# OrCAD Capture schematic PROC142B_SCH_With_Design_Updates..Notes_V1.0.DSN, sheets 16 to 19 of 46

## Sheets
16 14. CURRENT MEASUREMENT DEVICES: size C; title: SOC SUPPLY RAILS CURRENT MEASUREMENT DEVICES
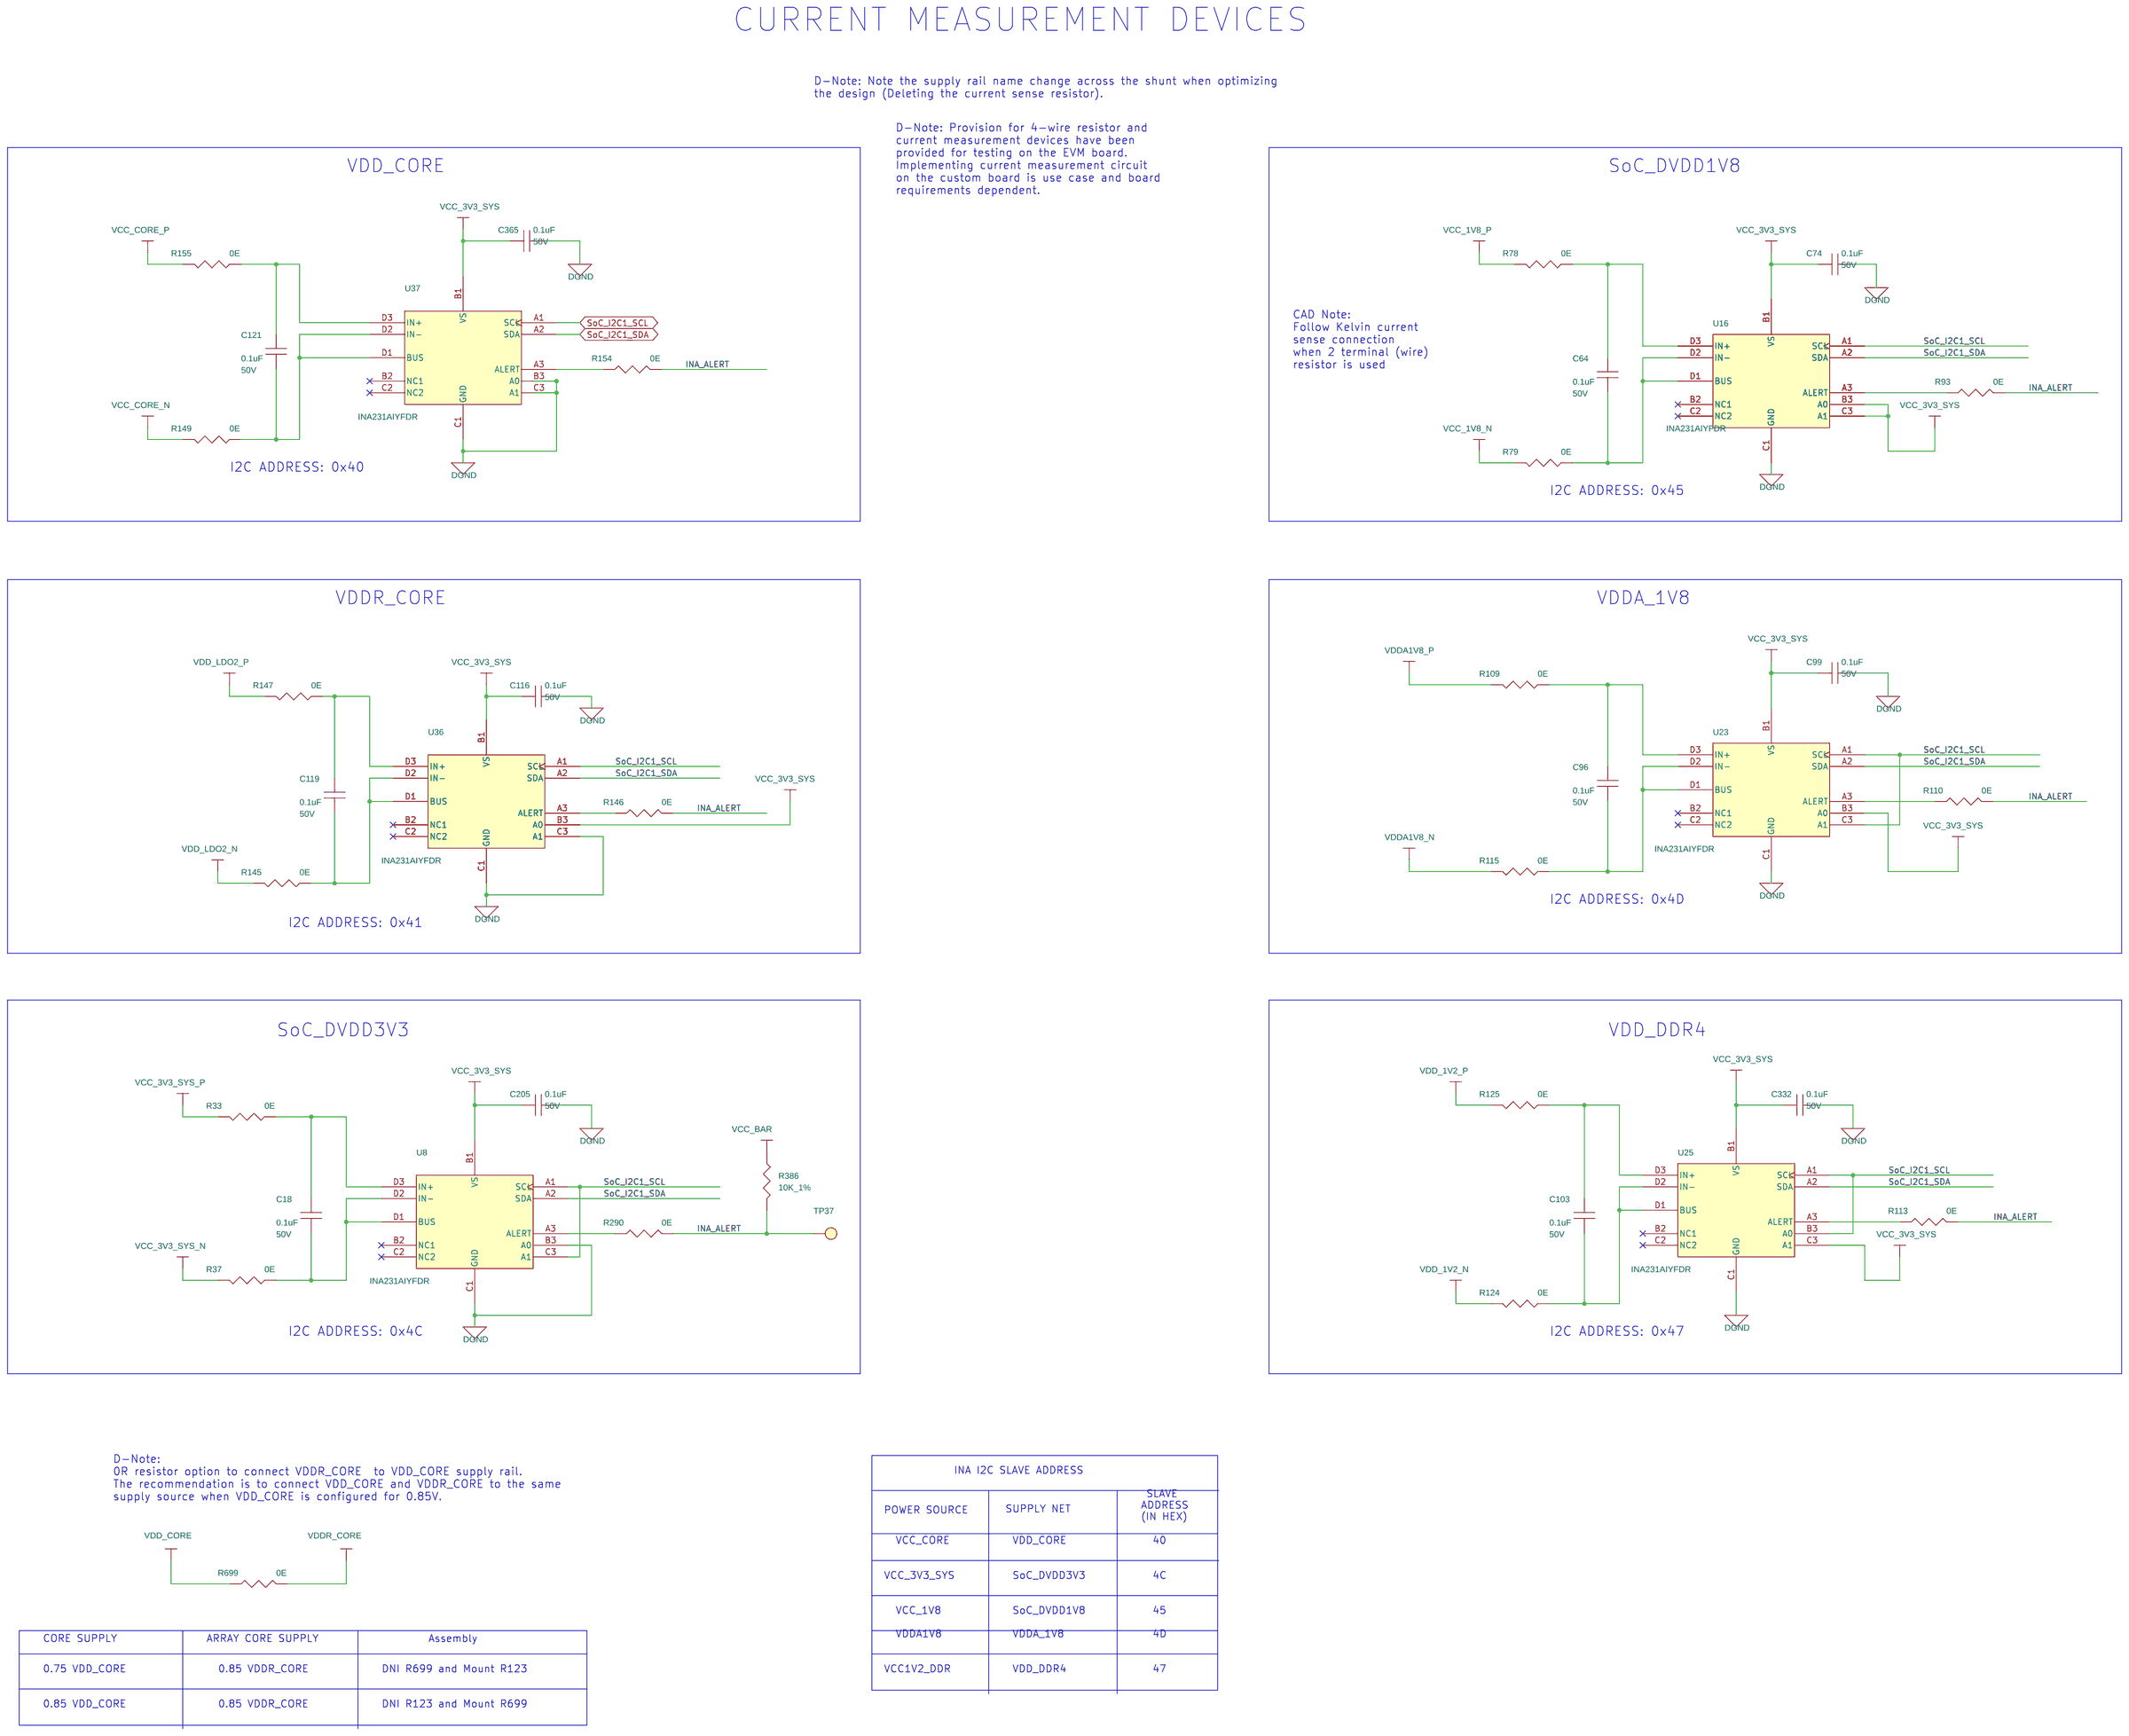
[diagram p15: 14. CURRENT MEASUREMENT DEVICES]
17 15. SOC POWER: size C; title: SOC POWER SUPPLIES, SUPPLY RAILS AND SOC GROUND VSS
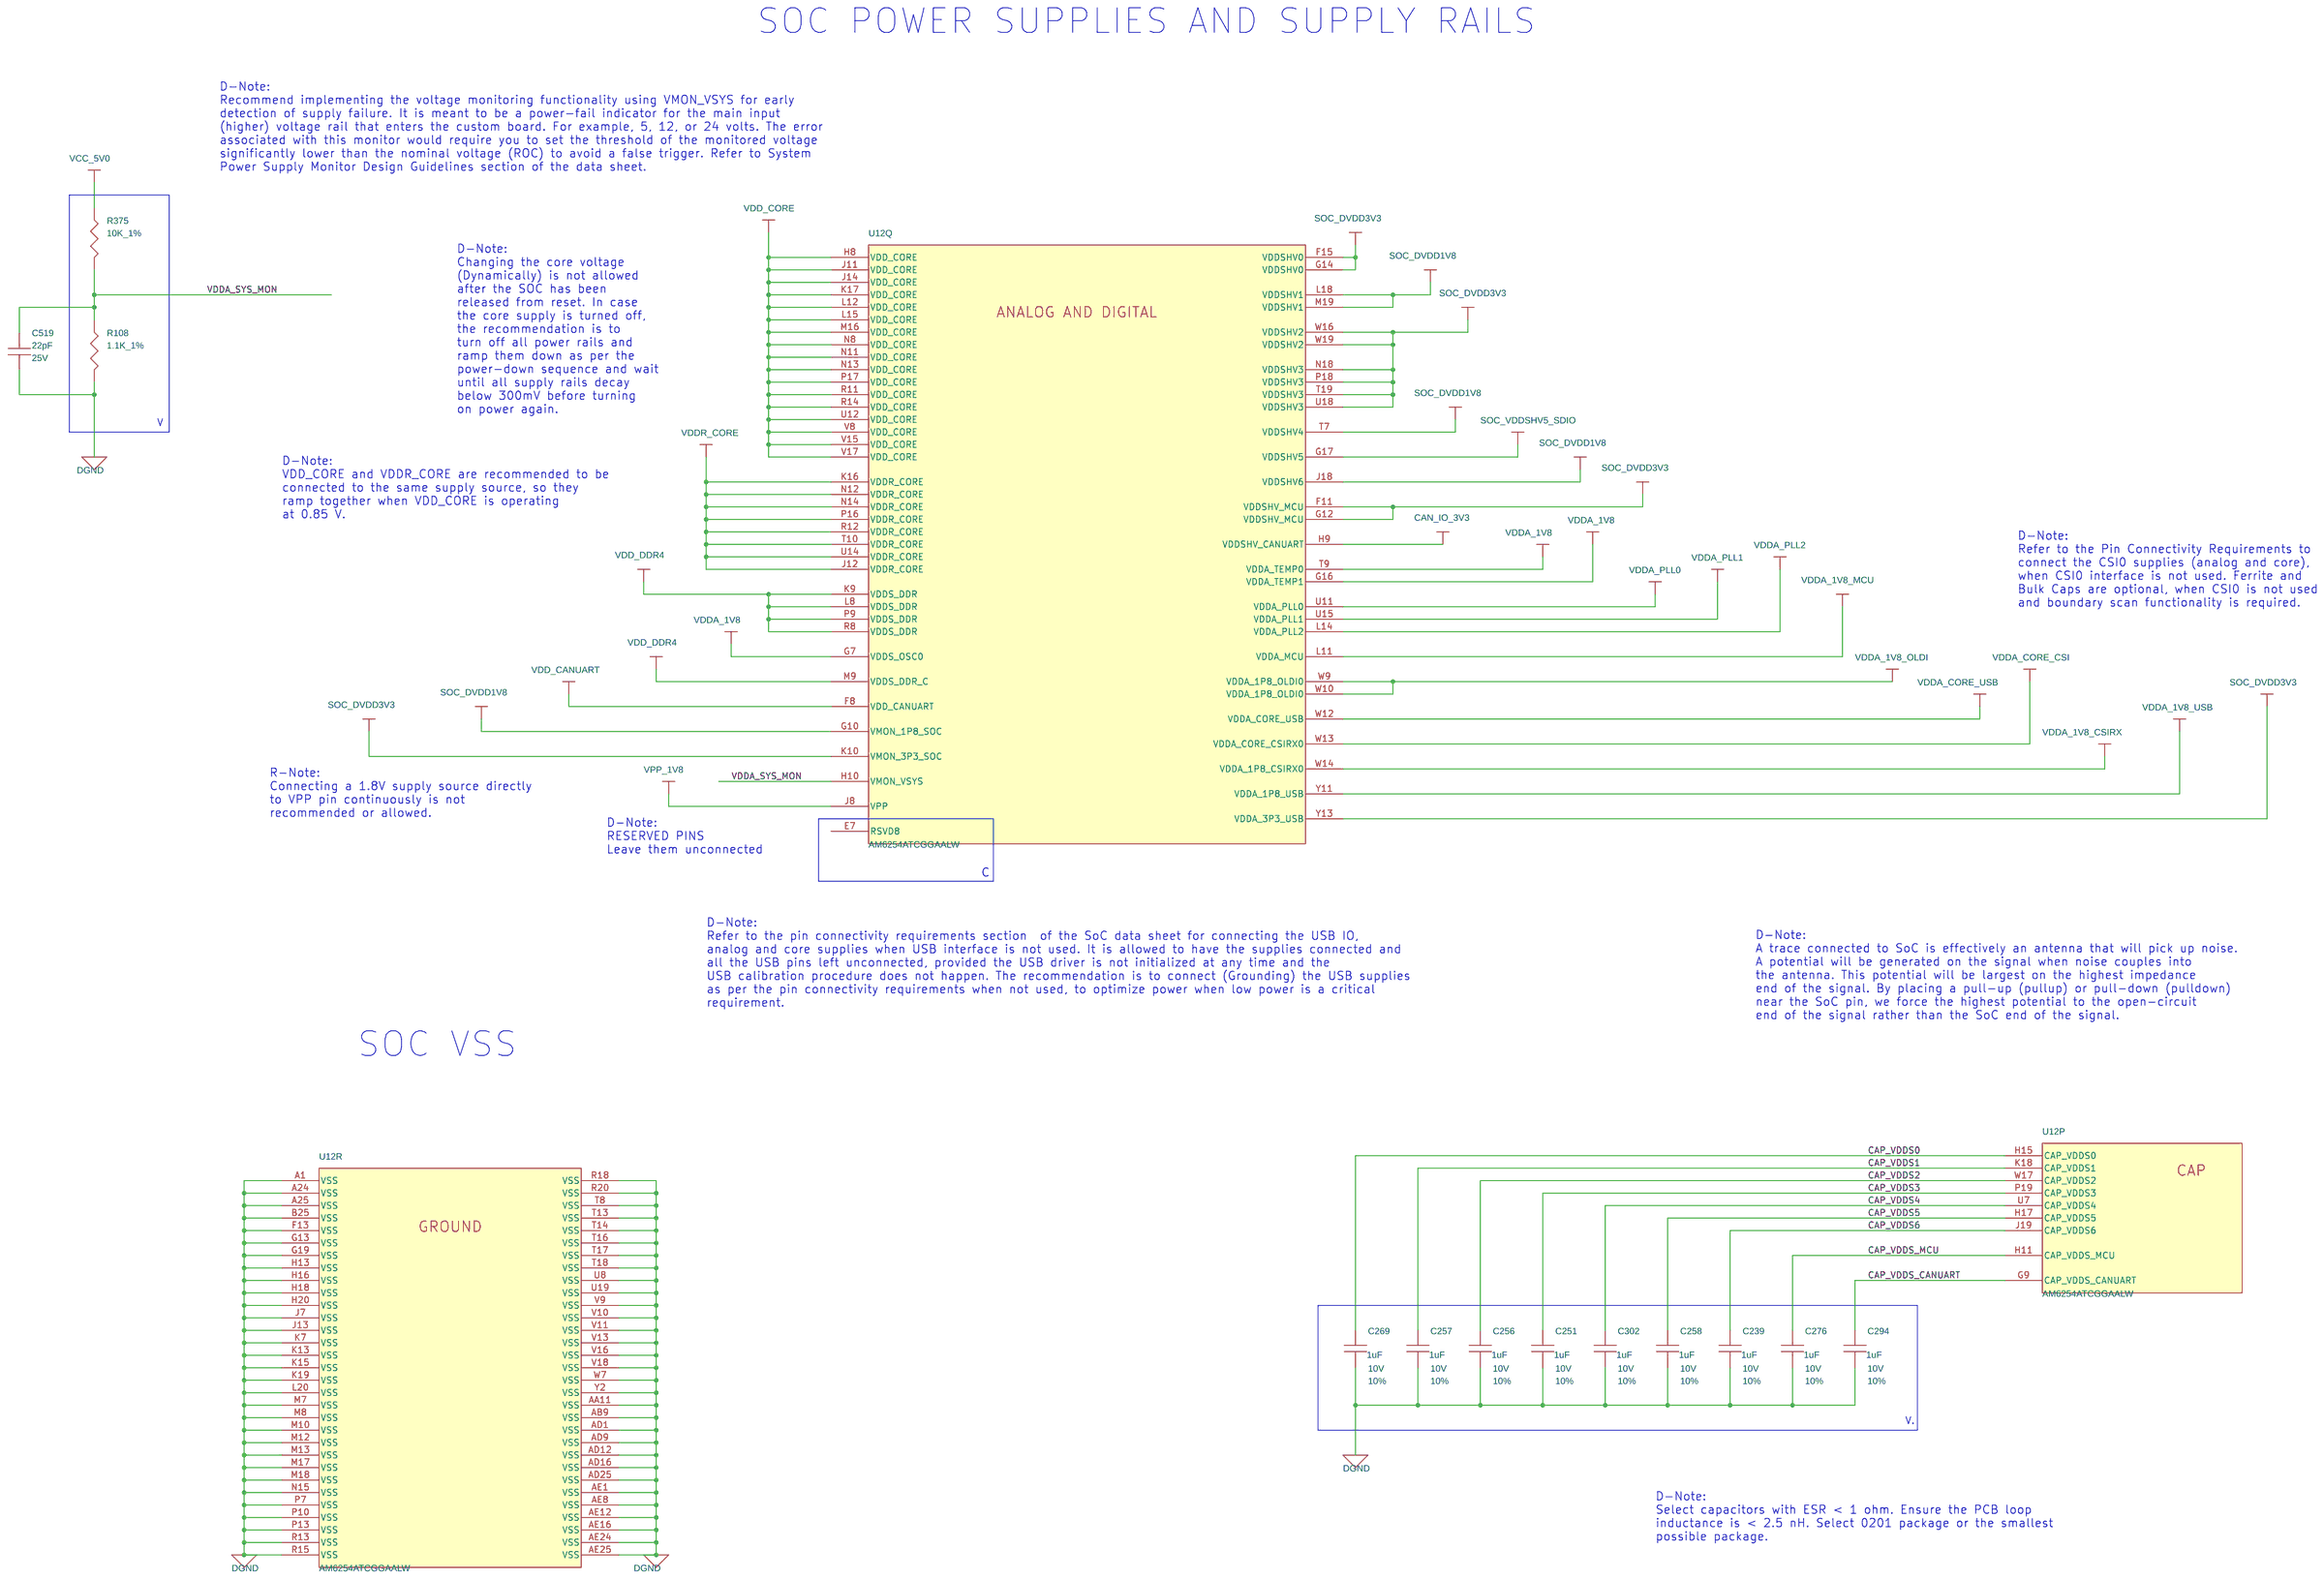
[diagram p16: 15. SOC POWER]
18 16. SOC POWER SUPPLIES-DECAPS 1: size C; title: SOC POWER SUPPLIES - DECAPS 1
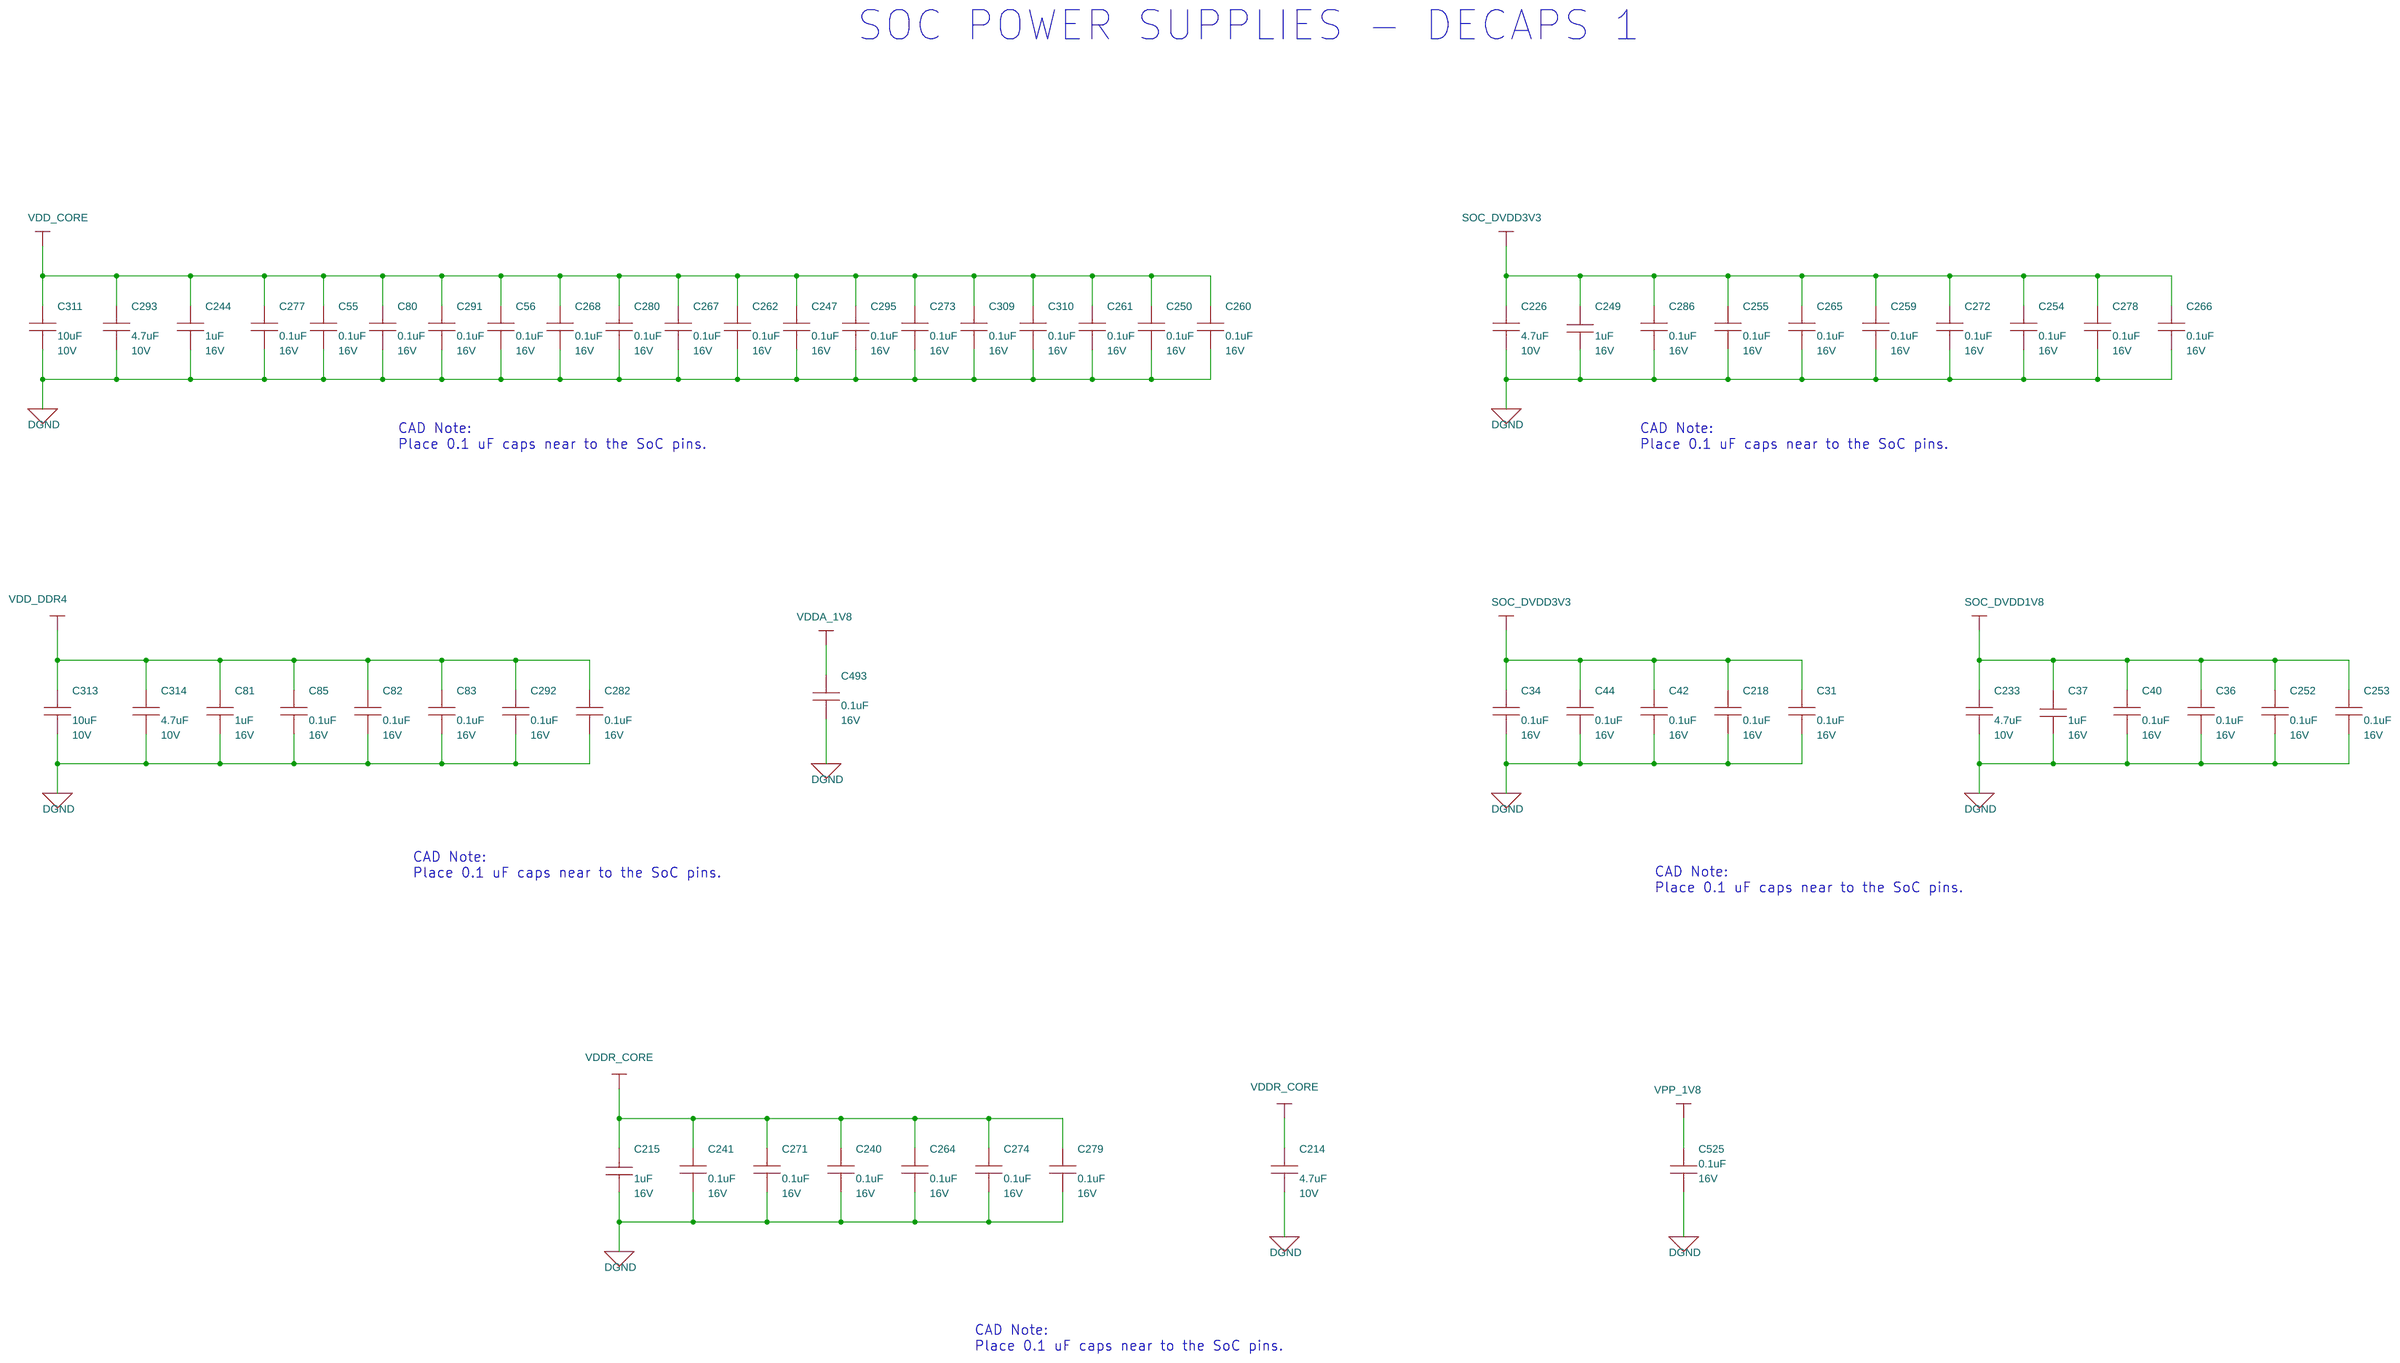
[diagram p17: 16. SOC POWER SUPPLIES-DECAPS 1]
19 18. DDR4 INTERFACE: size C; title: SOC DDRSS AND DDR4 MEMORY DEVICE INTERFACE
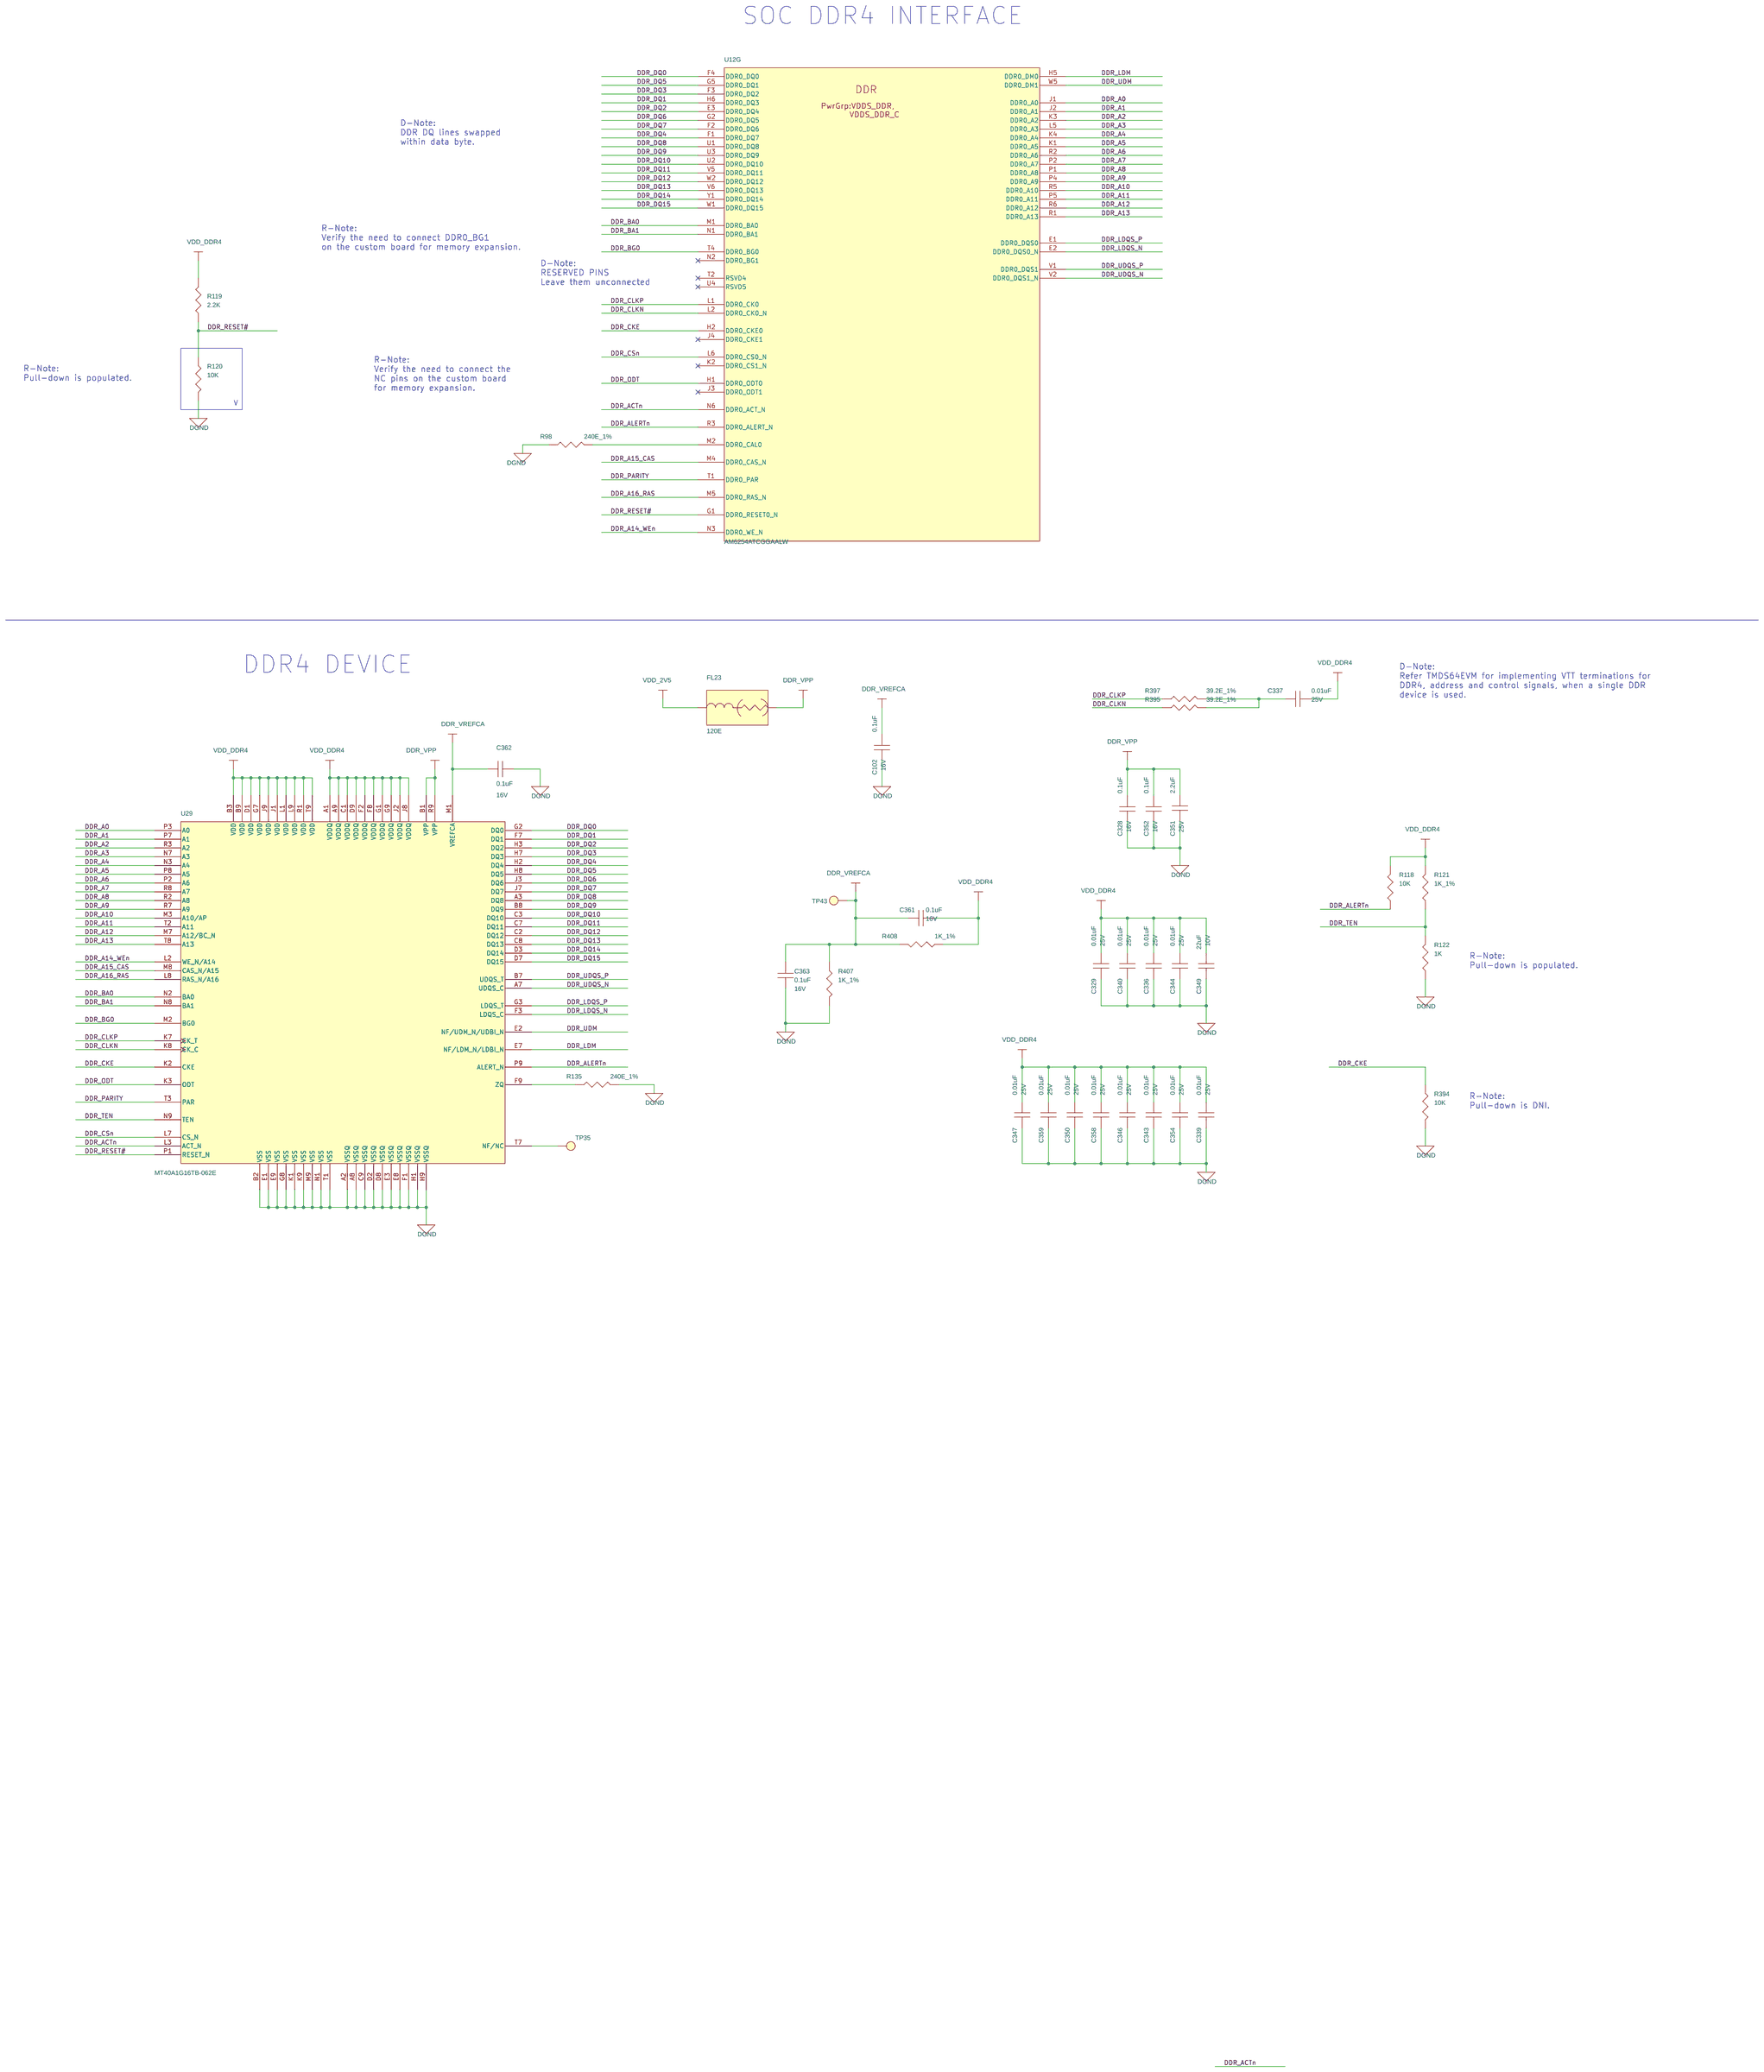
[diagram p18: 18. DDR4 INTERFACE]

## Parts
sheet 14. CURRENT MEASUREMENT DEVICES
C18  0.1uF  [CAP0402_0-75]
C64  0.1uF  [CAP0402_0-75]
C74  0.1uF  [CAP0402_0-75]
C96  0.1uF  [CAP0402_0-75]
C99  0.1uF  [CAP0402_0-75]
C103  0.1uF  [CAP0402_0-75]
C116  0.1uF  [CAP0402_0-75]
C119  0.1uF  [CAP0402_0-75]
C121  0.1uF  [CAP0402_0-75]
C205  0.1uF  [CAP0402_0-75]
C332  0.1uF  [CAP0402_0-75]
C365  0.1uF  [CAP0402_0-75]
R33  0E  [RES0402_0-5]
R37  0E  [RES0402_0-5]
R78  0E  [RES0402_0-5]
R79  0E  [RES0402_0-5]
R93  0E  [RES0402_0-5]
R109  0E  [RES0402_0-5]
R110  0E  [RES0402_0-5]
R113  0E  [RES0402_0-5]
R115  0E  [RES0402_0-5]
R124  0E  [RES0402_0-5]
R125  0E  [RES0402_0-5]
R145  0E  [RES0402_0-5]
R146  0E  [RES0402_0-5]
R147  0E  [RES0402_0-5]
R149  0E  [RES0402_0-5]
R154  0E  [RES0402_0-5]
R155  0E  [RES0402_0-5]
R290  0E  [RES0402_0-5]
R386  10K_1%  [RES0201_0-5]
R699  0E  [RES0805_0-75]
TP37  TP20_SMD  [TP20_SMD]
U8  INA231AIYFDR  [DSBGA12_15-74_60X70_0-4]
U16  INA231AIYFDR  [DSBGA12_15-74_60X70_0-4]
U23  INA231AIYFDR  [DSBGA12_15-74_60X70_0-4]
U25  INA231AIYFDR  [DSBGA12_15-74_60X70_0-4]
U36  INA231AIYFDR  [DSBGA12_15-74_60X70_0-4]
U37  INA231AIYFDR  [DSBGA12_15-74_60X70_0-4]
sheet 15. SOC POWER
C239  1uF  [CAP0201_0-5]
C251  1uF  [CAP0201_0-5]
C256  1uF  [CAP0201_0-5]
C257  1uF  [CAP0201_0-5]
C258  1uF  [CAP0201_0-5]
C269  1uF  [CAP0201_0-5]
C276  1uF  [CAP0201_0-5]
C294  1uF  [CAP0201_0-5]
C302  1uF  [CAP0201_0-5]
C519  22pF  [CAP0201_0-5]
R108  1.1K_1%  [RES0402_0-5]
R375  10K_1%  [RES0402_0-5]
sheet 16. SOC POWER SUPPLIES-DECAPS 1
C31  0.1uF  [CAP0201_0-5]
C34  0.1uF  [CAP0201_0-5]
C36  0.1uF  [CAP0201_0-5]
C37  1uF  [CAP0201_0-5]
C40  0.1uF  [CAP0201_0-5]
C42  0.1uF  [CAP0201_0-5]
C44  0.1uF  [CAP0201_0-5]
C55  0.1uF  [CAP0201_0-5]
C56  0.1uF  [CAP0201_0-5]
C80  0.1uF  [CAP0201_0-5]
C81  1uF  [CAP0201_0-5]
C82  0.1uF  [CAP0201_0-5]
C83  0.1uF  [CAP0201_0-5]
C85  0.1uF  [CAP0201_0-5]
C214  4.7uF  [CAP0402_0-75]
C215  1uF  [CAP0201_0-5]
C218  0.1uF  [CAP0201_0-5]
C226  4.7uF  [CAP0402_0-75]
C233  4.7uF  [CAP0402_0-75]
C240  0.1uF  [CAP0201_0-5]
C241  0.1uF  [CAP0201_0-5]
C244  1uF  [CAP0201_0-5]
C247  0.1uF  [CAP0201_0-5]
C249  1uF  [CAP0201_0-5]
C250  0.1uF  [CAP0201_0-5]
C252  0.1uF  [CAP0201_0-5]
C253  0.1uF  [CAP0201_0-5]
C254  0.1uF  [CAP0201_0-5]
C255  0.1uF  [CAP0201_0-5]
C259  0.1uF  [CAP0201_0-5]
C260  0.1uF  [CAP0201_0-5]
C261  0.1uF  [CAP0201_0-5]
C262  0.1uF  [CAP0201_0-5]
C264  0.1uF  [CAP0201_0-5]
C265  0.1uF  [CAP0201_0-5]
C266  0.1uF  [CAP0201_0-5]
C267  0.1uF  [CAP0201_0-5]
C268  0.1uF  [CAP0201_0-5]
C271  0.1uF  [CAP0201_0-5]
C272  0.1uF  [CAP0201_0-5]
C273  0.1uF  [CAP0201_0-5]
C274  0.1uF  [CAP0201_0-5]
C277  0.1uF  [CAP0201_0-5]
C278  0.1uF  [CAP0201_0-5]
C279  0.1uF  [CAP0201_0-5]
C280  0.1uF  [CAP0201_0-5]
C282  0.1uF  [CAP0201_0-5]
C286  0.1uF  [CAP0201_0-5]
C291  0.1uF  [CAP0201_0-5]
C292  0.1uF  [CAP0201_0-5]
C293  4.7uF  [CAP0402_0-75]
C295  0.1uF  [CAP0201_0-5]
C309  0.1uF  [CAP0201_0-5]
C310  0.1uF  [CAP0201_0-5]
C311  10uF  [CAP0402_0-75]
C313  10uF  [CAP0402_0-75]
C314  4.7uF  [CAP0402_0-75]
C493  0.1uF  [CAP0201_0-5]
C525  0.1uF  [CAP0201_0-5]
sheet 18. DDR4 INTERFACE
C102  0.1uF  [CAP0201_0-5]
C328  0.1uF  [CAP0201_0-5]
C329  0.01uF  [CAP0201_0-5]
C336  0.01uF  [CAP0201_0-5]
C337  0.01uF  [CAP0201_0-5]
C339  0.01uF  [CAP0201_0-5]
C340  0.01uF  [CAP0201_0-5]
C343  0.01uF  [CAP0201_0-5]
C344  0.01uF  [CAP0201_0-5]
C346  0.01uF  [CAP0201_0-5]
C347  0.01uF  [CAP0201_0-5]
C349  22uF  [CAP0603_1]
C350  0.01uF  [CAP0201_0-5]
C351  2.2uF  [CAP0402_0-75]
C352  0.1uF  [CAP0201_0-5]
C354  0.01uF  [CAP0201_0-5]
C358  0.01uF  [CAP0201_0-5]
C359  0.01uF  [CAP0201_0-5]
C361  0.1uF  [CAP0201_0-5]
C362  0.1uF  [CAP0201_0-5]
C363  0.1uF  [CAP0201_0-5]
FL23  120E  [EMIFIL_BLM15A_0402_0-6]
R98  240E_1%  [RES0402_0-5]
R118  10K  [RES0201_0-5]
R119  2.2K  [RES0201_0-5]
R120  10K  [RES0402_0-5]
R121  1K_1%  [RES0402_0-5]
R122  1K  [RES0402_0-5]
R135  240E_1%  [RES0402_0-5]
R394  10K  [RES0201_0-5]
R395  39.2E_1%  [RES0402_0-5]
R397  39.2E_1%  [RES0402_0-5]
R407  1K_1%  [RES0201_0-5]
R408  1K_1%  [RES0201_0-5]
TP35  TP20_SMD  [TP20_SMD]
TP43  TP20_SMD  [TP20_SMD]
U29  MT40A1G16TB-062E  [FBGA96_31-49_300X520_1-2]
sheet 43. HDMI INTERFACE
U12  AM6254ATCGGAALW  [BGA425_19-68_510X510_0-7]  (sections A,B,C,D,E,F,G,H,I,J,K,L,M,N,O,P,Q,R)

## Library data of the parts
C18 C64 C74 C96 C99 C103 C116 C119 C121 C205 C332 C365 = CAP: CAP CERAMIC 0.1uF 50V 10% X7R 0402; Alt_Mfr_name: YAGEO AMERICA; Alt_Mfr_part_number: CC0402KRX5R8BB104; Chkd/date: MANIRAJA/261020; Crtd /date: ALVY/211020; Custom_Duty: 15%; Customs_HS_Code: 85322990; Distributor_name: DIGIKEY; Distributor_part_number: 490-10700-1-ND; Footprint Path: Y:\MIS_DATABASE\Library\ALTIUM_TOOL\PCB_FOOTPRINTS\Altium_Footprint_Lib.PcbLib; Height: 0.55MM; Library Path: Y:\MIS_DATABASE\Library\ALTIUM_TOOL\SCHEMATICS_PARTS\MS_DISCRETE_Library.schlib; Mfr_name: MURATA; Mfr_part_number: GRM155R71H104KE14D; Mistral Part No: 120011100014-R; Package: 0402; Part_type: CAPACITORS\CERAMIC; Project: J7_CP; RoHS: RoHS; Temperature: -55°C+125°C; Tolerance: 10%; Voltage: 50V; Wattage: NA; Weight: 3.1mg; Datasheet: Y:\MIS_DATABASE\DATASHEETS\CAPACITORS\GRM155R71H104KE14.PDF
R33 R37 R78 R79 R93 R109 R110 R113 R115 R124 R125 R145-R147 R149 R154 R155 R290 = RESISTOR: RES 0E 1/16W JUMPER 0402; Chkd/date: VASANTHA/201216; Crtd /date: MUDDU/190810; Custom_Duty: 15%; Customs_HS_Code: 85332119; Distributor_name: DIGIKEY; Distributor_part_number: 541-0.0JCT-ND; Footprint Path: Y:\MIS_DATABASE\Library\ALTIUM_TOOL\PCB_FOOTPRINTS\Altium_Footprint_Lib.PcbLib; Height: 0.40MM; Library Path: Y:\MIS_DATABASE\Library\ALTIUM_TOOL\SCHEMATICS_PARTS\MS_DISCRETE_Library.schlib; Mfr_name: VISHAY; Mfr_part_number: CRCW04020000Z0ED; Mistral Part No: 110010080019-R; Package: 0402; Part_type: RESISTORS\FIXED; Project: PB_BUGBASE; RoHS: RoHS; Temperature: -55°C+155°C; Tolerance: NA; Voltage: NA; Wattage: 1/16W; Weight: 0.65mg; Datasheet: Y:\MIS_DATABASE\DATASHEETS\RESISTORS\CRCW0603.PDF
R386 = RESISTOR: RES 10K 1/20W 1% 0201; Chkd/date: VASANTHA/270117; Crtd /date: MANIRAJA/270117; Custom_Duty: 15%; Customs_HS_Code: 85332119; Distributor_name: DIGIKEY; Distributor_part_number: 311-10.0KMCT-ND; Footprint Path: Y:\MIS_DATABASE\Library\ALTIUM_TOOL\PCB_FOOTPRINTS\Altium_Footprint_Lib.PcbLib; Height: 0.26MM; Library Path: Y:\MIS_DATABASE\Library\ALTIUM_TOOL\SCHEMATICS_PARTS\MS_DISCRETE_Library.schlib; Mfr_name: YAGEO AMERICA; Mfr_part_number: RC0201FR-0710KL; Mistral Part No: 110011040018-R; Package: 0201; Part_type: RESISTORS\FIXED; Project: GOLDEN-I LITE; RoHS: RoHS; Temperature: -55°C+125°C; Tolerance: 1%; Voltage: NA; Wattage: 1/20W; Weight: 0.17mg; Datasheet: Y:\MIS_DATABASE\DATASHEETS\RESISTORS\RCXXXXL-SER_MAR18.PDF
R699 = RESISTOR: RES 0E 1/8W 5% 0805; Chkd/date: VASANTHA/130416; Crtd /date: JEBRAN/020316; Custom_Duty: 15%; Customs_HS_Code: 85332119; Distributor_name: DIGIKEY; Distributor_part_number: 311-0.0ARCT-ND; Footprint Path: Y:\MIS_DATABASE\Library\ALTIUM_TOOL\PCB_FOOTPRINTS\Altium_Footprint_Lib.PcbLib; Height: 0.60MM; Library Path: Y:\MIS_DATABASE\Library\ALTIUM_TOOL\SCHEMATICS_PARTS\MS_DISCRETE_Library.schlib; Mfr_name: YAGEO AMERICA; Mfr_part_number: RC0805JR-070RL; Mistral Part No: 110009030074-R; Package: 0805; Part_type: RESISTORS\FIXED; Project: ZK_BIOMETRIC; RoHS: RoHS; Temperature: -55°C+155°C; Tolerance: 5%; Voltage: NA; Wattage: 1/8W; Weight: 5.5mg; Datasheet: Y:\MIS_DATABASE\DATASHEETS\RESISTORS\RCXXXXL-SER_MAR18.PDF
TP35 TP37 TP43 = TESTPOINT: TESTPOINT CIR 20 SMD; Chkd/date: SHREESHAIL/171006; Crtd /date: MAZHAR/171006; Custom_Duty: NA; Customs_HS_Code: NA; Distributor_name: NA; Distributor_part_number: NA; Footprint Path: Y:\MIS_DATABASE\Library\ALTIUM_TOOL\PCB_FOOTPRINTS\Altium_Footprint_Lib.PcbLib; Height: NA; Library Path: Y:\MIS_DATABASE\Library\ALTIUM_TOOL\SCHEMATICS_PARTS\MS_DISCRETE_Library.schlib; MECHANICAL 3D STEP FILE: NA; Mfr_name: LOCAL; Mistral Part No: NA; Package: SMD; Project: BT MODULE_CSRBC04; RoHS: NA; Temperature: NA; Tolerance: NA; Voltage: NA; Wattage: NA; Weight: NA; Datasheet: NA
U8 U16 U23 U25 U36 U37 = INA231_DSBGA12: IC HIGH OR LOW SIDE MEASUREMENT BI-DIR CURRENT AND POWER MONITOR WITH 1.8V I2C INTERFACE DSBGA12; Chkd/date: MANIRAJA/250821; Crtd /date: ALVY/250821; Custom_Duty: 15%; Customs_HS_Code: 85423100; Distributor_name: DIGIKEY; Distributor_part_number: 296-49645-1-ND; Footprint Path: Y:\MIS_DATABASE\Library\ALTIUM_TOOL\PCB_FOOTPRINTS\Altium_Footprint_Lib.PcbLib; Height: 0.40MM; Library Path: Y:\MIS_DATABASE\Library\ALTIUM_TOOL\SCHEMATICS_PARTS\MS_MISCPOWER_Library.schlib; Mfr_name: TEXAS INSTRUMENTS; Mistral Part No: 142021080022-R; Package: DSBGA12; Part_type: ICS\POWER\MANAGEMENT; Project: TI_AM62x SVB_BRD; RoHS: RoHS; Temperature: -40°C+125°C; Tolerance: NA; Voltage: NA; Wattage: NA; Weight: 200mg; Datasheet: Y:\MIS_DATABASE\DATASHEETS\ICS\POWER\INA231XXX.PDF
C239 C251 C256-C258 C269 C276 C294 C302 = CAP: CAP CERAMIC 1uF 10V 10% X5R 0201; Alternate_mfr_name_A: MURATA; Alternate_mfr_part_number_A: GRM033R61C105ME15D; Chkd/date: MANIRAJA/130519; Crtd /date: ALVY/100519; Custom_Duty: 15%; Customs_HS_Code: 85322990; Distributor_name: DIGIKEY; Distributor_part_number: 1276-6795-1-ND; Footprint Path: Y:\MIS_DATABASE\Library\ALTIUM_TOOL\PCB_FOOTPRINTS\Altium_Footprint_Lib.PcbLib; Height: 0.35MM; Library Path: Y:\MIS_DATABASE\Library\ALTIUM_TOOL\SCHEMATICS_PARTS\MS_DISCRETE_Library.schlib; Mfr_name: SAMSUNG; Mfr_part_number: CL03A105KP3NSNC; Mistral Part No: 120019050005-R; Package: 0201; Part_type: CAPACITORS\CERAMIC; Project: BRUKER_SD820_COMMONDO; RoHS: RoHS; Temperature: -55°C+85°C; Tolerance: 10%; Voltage: 10V; Wattage: NA; Weight: NA; Datasheet: Y:\MIS_DATABASE\DATASHEETS\CAPACITORS\CL03A105KP3NSNC.PDF
C519 = CAP: CAP CERAMIC 22pF 25V 1% C0G(NP0) 0201; Chkd/date: MANIRAJA/270721; Crtd /date: ALVY/260721; Custom_Duty: 15%; Customs_HS_Code: 85322990; Distributor_name: DIGIKEY; Distributor_part_number: 490-14545-1-ND; Footprint Path: Y:\MIS_DATABASE\Library\ALTIUM_TOOL\PCB_FOOTPRINTS\Altium_Footprint_Lib.PcbLib; Height: 0.33MM; Library Path: Y:\MIS_DATABASE\Library\ALTIUM_TOOL\SCHEMATICS_PARTS\MS_DISCRETE_Library.schlib; Mfr_name: MURATA; Mfr_part_number: GRM0335C1E220FA01D; Mistral Part No: 120021070019-R; Package: 0201; Part_type: CAPACITORS\CERAMIC; Project: TI_AM335x SK_BRD; RoHS: RoHS; Temperature: -55°C+125°C; Tolerance: 1%; Voltage: 25V; Wattage: NA; Weight: 0.33mg; Datasheet: Y:\MIS_DATABASE\DATASHEETS\CAPACITORS\GRM0335C1E220FA01.PDF
R108 = RESISTOR: RES 1.1K 1/16W 1% 0402; Chkd/date: MANIRAJA/081020; Crtd /date: ALVY/081020; Custom_Duty: 15%; Customs_HS_Code: 85332119; Distributor_name: DIGIKEY; Distributor_part_number: 541-1.10KLCT-ND; Footprint Path: Y:\MIS_DATABASE\Library\ALTIUM_TOOL\PCB_FOOTPRINTS\Altium_Footprint_Lib.PcbLib; Height: 0.40MM; Library Path: Y:\MIS_DATABASE\Library\ALTIUM_TOOL\SCHEMATICS_PARTS\MS_DISCRETE_Library.schlib; Mfr_name: VISHAY; Mfr_part_number: CRCW04021K10FKED; Mistral Part No: 110010120009-R; Package: 0402; Part_type: RESISTORS\FIXED; Project: VAGG_SBC_BRD; RoHS: RoHS; Temperature: -55°C+155°C; Tolerance: 1%; Voltage: NA; Wattage: 1/16W; Weight: 0.65mg; Datasheet: Y:\MIS_DATABASE\DATASHEETS\RESISTORS\CRCW0603.PDF
R375 = RESISTOR: RES 10K 1/10W 1% 0402; Chkd/date: MANIRAJA/190218; Crtd /date: NAVEED/280515; Custom_Duty: 15%; Customs_HS_Code: 85332119; Distributor_name: DIGIKEY; Distributor_part_number: P10.0KLCT-ND; Footprint Path: Y:\MIS_DATABASE\Library\ALTIUM_TOOL\PCB_FOOTPRINTS\Altium_Footprint_Lib.PcbLib; Height: 0.40MM; Library Path: Y:\MIS_DATABASE\Library\ALTIUM_TOOL\SCHEMATICS_PARTS\MS_DISCRETE_Library.schlib; Mfr_name: PANASONIC-ECG; Mfr_part_number: ERJ-2RKF1002X; Mistral Part No: 110015050015-R; Package: 0402; Part_type: RESISTORS\FIXED; Project: DLRL NARROW BAND; RoHS: RoHS; Temperature: -55°C+155°C; Tolerance: 1%; Voltage: NA; Wattage: 1/10W; Weight: 0.8mg; Datasheet: Y:\MIS_DATABASE\DATASHEETS\RESISTORS\PAN-ERJSER_NOV17.PDF
C31 C34 C36 C40 C42 C44 C55 C56 C80 C82 C83 C85 C102 C218 C240 C241 C247 C250 C252-C255 C259-C262 C264-C268 C271-C274 C277-C280 C282 C286 C291 C292 C295 C309 C310 C328 C352 C493 C525 = CAP: CAP CERAMIC 0.1uF 16V 10% X5R 0201; Chkd/date: MANIRAJA/230118; Crtd /date: MANIRAJA/230118; Custom_Duty: 15%; Customs_HS_Code: 85322990; Distributor_name: DIGIKEY; Distributor_part_number: 490-14305-1-ND; Footprint Path: Y:\MIS_DATABASE\Library\ALTIUM_TOOL\PCB_FOOTPRINTS\Altium_Footprint_Lib.PcbLib; Height: 0.33MM; Library Path: Y:\MIS_DATABASE\Library\ALTIUM_TOOL\SCHEMATICS_PARTS\MS_DISCRETE_Library.schlib; Mfr_name: MURATA; Mfr_part_number: GRM033R61C104KE14D; Mistral Part No: 120009030072-R; Package: 0201; Part_type: CAPACITORS\CERAMIC; Project: TI_MAXIE_CPB; RoHS: RoHS; Temperature: -55°C+85°C; Tolerance: 10%; Voltage: 16V; Wattage: NA; Weight: 0.33mg; Datasheet: Y:\MIS_DATABASE\DATASHEETS\CAPACITORS\GRM033R61C104KE14.PDF
C37 C81 C215 C244 C249 = CAP: CAP CERAMIC 1uF 16V 20% X5R 0201; Chkd/date: MANIRAJA/300520; Crtd /date: ALVY/260520; Custom_Duty: 15%; Customs_HS_Code: 85322990; Distributor_name: DIGIKEY; Distributor_part_number: 490-18654-1-ND; Footprint Path: Y:\MIS_DATABASE\Library\ALTIUM_TOOL\PCB_FOOTPRINTS\Altium_Footprint_Lib.PcbLib; Height: 0.39MM; Library Path: Y:\MIS_DATABASE\Library\ALTIUM_TOOL\SCHEMATICS_PARTS\MS_DISCRETE_Library.schlib; Mfr_name: MURATA; Mfr_part_number: GRM033R61C105ME15D; Mistral Part No: 120018090038-R; Package: 0201; Part_type: CAPACITORS\CERAMIC; Project: QCS610_NANOSOM; RoHS: RoHS; Temperature: -55°C+85°C; Tolerance: 20%; Voltage: 16V; Wattage: NA; Weight: 0.33mg; Datasheet: Y:\MIS_DATABASE\DATASHEETS\CAPACITORS\GRM033R61C105ME15.PDF
C214 C226 C233 C293 C314 = CAP: CAP CERAMIC 4.7uF 10V 20% X5R 0402; Chkd/date: MANIRAJA/110718; Crtd /date: ALVY/110718; Custom_Duty: 15%; Customs_HS_Code: 85322990; Distributor_name: DIGIKEY; Distributor_part_number: 490-14306-1-ND; Footprint Path: Y:\MIS_DATABASE\Library\ALTIUM_TOOL\PCB_FOOTPRINTS\Altium_Footprint_Lib.PcbLib; Height: 0.65MM; Library Path: Y:\MIS_DATABASE\Library\ALTIUM_TOOL\SCHEMATICS_PARTS\MS_DISCRETE_Library.schlib; Mfr_name: MURATA; Mfr_part_number: GRM155R61A475MEAAD; Mistral Part No: 120012060002-R; Package: 0402; Part_type: CAPACITORS\CERAMIC; Project: TI_J7SVB_PCIE_ADD-ON-CARD; RoHS: RoHS; Temperature: -55°C+85°C; Tolerance: 20%; Voltage: 10V; Wattage: NA; Weight: 14mg; Datasheet: Y:\MIS_DATABASE\DATASHEETS\CAPACITORS\GRM155R61A475MEAAD.PDF
C311 C313 = CAP: CAP CERAMIC 10uF 10V 20% X5R 0402; Chkd/date: MANIRAJA/300520; Crtd /date: ALVY/260520; Custom_Duty: 15%; Customs_HS_Code: 85322990; Distributor_name: DIGIKEY; Distributor_part_number: 490-GRM155R61A106ME11DTR-ND; Footprint Path: Y:\MIS_DATABASE\Library\ALTIUM_TOOL\PCB_FOOTPRINTS\Altium_Footprint_Lib.PcbLib; Height: 0.55MM; Library Path: Y:\MIS_DATABASE\Library\ALTIUM_TOOL\SCHEMATICS_PARTS\MS_DISCRETE_Library.schlib; Mfr_name: MURATA; Mfr_part_number: GRM155R61A106ME11D; Mistral Part No: 120013110019-R; Package: 0402; Part_type: CAPACITORS\CERAMIC; Project: QCS610_NANOSOM; RoHS: RoHS; Temperature: -55°C+85°C; Tolerance: 20%; Voltage: 10V; Wattage: NA; Weight: 3.1mg; Datasheet: Y:\MIS_DATABASE\DATASHEETS\CAPACITORS\MURATA-GXX-SER_NOV17.PDF
C329 C336 C337 C339 C340 C343 C344 C346 C347 C350 C354 C358 C359 = CAP: CAP CERAMIC 0.01uF 25V 10% X5R 0201; Chkd/date: MANIRAJA/230118; Crtd /date: MANIRAJA/230118; Custom_Duty: 15%; Customs_HS_Code: 85322990; Distributor_name: DIGIKEY; Distributor_part_number: GRM033R61E103KA12J-ND; Footprint Path: Y:\MIS_DATABASE\Library\ALTIUM_TOOL\PCB_FOOTPRINTS\Altium_Footprint_Lib.PcbLib; Height: 0.33MM; Library Path: Y:\MIS_DATABASE\Library\ALTIUM_TOOL\SCHEMATICS_PARTS\MS_DISCRETE_Library.schlib; Mfr_name: MURATA; Mfr_part_number: GRM033R61E103KA12J; Mistral Part No: 120018010007-R; Package: 0201; Part_type: CAPACITORS\CERAMIC; Project: TI_MAXIE_CPB; RoHS: RoHS; Temperature: -55°C+85°C; Tolerance: 10%; Voltage: 25V; Wattage: NA; Weight: 0.33mg; Datasheet: Y:\MIS_DATABASE\DATASHEETS\CAPACITORS\GRM033R61E103KA12.PDF
C349 = CAP: CAP CERAMIC 22uF 10V 20% X5R 0603; Chkd/date: MANIRAJA/230118; Crtd /date: MANIRAJA/230118; Custom_Duty: 15%; Customs_HS_Code: 85322990; Distributor_name: DIGIKEY; Distributor_part_number: 490-10476-1-ND; Footprint Path: Y:\MIS_DATABASE\Library\ALTIUM_TOOL\PCB_FOOTPRINTS\Altium_Footprint_Lib.PcbLib; Height: 1.00MM; Library Path: Y:\MIS_DATABASE\Library\ALTIUM_TOOL\SCHEMATICS_PARTS\MS_DISCRETE_Library.schlib; Mfr_name: MURATA; Mfr_part_number: GRM188R61A226ME15D; Mistral Part No: 120014100009-R; Package: 0603; Part_type: CAPACITORS\CERAMIC; Project: TI_MAXIE_CPB; RoHS: RoHS; Temperature: -55°C+85°C; Tolerance: 20%; Voltage: 10V; Wattage: NA; Weight: 6.3mg; Datasheet: Y:\MIS_DATABASE\DATASHEETS\CAPACITORS\GRM188R61A226ME15.PDF
C351 = CAP: CAP CERAMIC 2.2uF 25V 10% X5R 0402; Chkd/date: ALVY/010721; Crtd /date: MANIRAJA/010721; Custom_Duty: 15%; Customs_HS_Code: 85322990; Distributor_name: DIGIKEY; Distributor_part_number: 490-12703-1-ND; Footprint Path: Y:\MIS_DATABASE\Library\ALTIUM_TOOL\PCB_FOOTPRINTS\Altium_Footprint_Lib.PcbLib; Height: 0.70MM; Library Path: Y:\MIS_DATABASE\Library\ALTIUM_TOOL\SCHEMATICS_PARTS\MS_DISCRETE_Library.schlib; Mfr_name: MURATA; Mfr_part_number: GRM155R61E225KE11D; Mistral Part No: 120015120001-R; Package: 0402; Part_type: CAPACITORS\CERAMIC; Project: TI_AM263X_CC; RoHS: RoHS; Temperature: -55°C+85°C; Tolerance: 10%; Voltage: 25V; Wattage: NA; Weight: 1.5mg; Datasheet: Y:\MIS_DATABASE\DATASHEETS\CAPACITORS\GRM155R61E225KE11.PDF
C361-C363 = CAP: CAP CERAMIC 0.1uF 16V 10% X5R 0201; Alt_Mfr_name: YAGEO AMERICA; Alt_Mfr_part_number: CC0402KRX5R8BB104; Chkd/date: MANIRAJA/230118; Crtd /date: MANIRAJA/230118; Custom_Duty: 15%; Customs_HS_Code: 85322990; Distributor_name: DIGIKEY; Distributor_part_number: 490-14305-1-ND; Footprint Path: Y:\MIS_DATABASE\Library\ALTIUM_TOOL\PCB_FOOTPRINTS\Altium_Footprint_Lib.PcbLib; Height: 0.33MM; Library Path: Y:\MIS_DATABASE\Library\ALTIUM_TOOL\SCHEMATICS_PARTS\MS_DISCRETE_Library.schlib; Mfr_name: MURATA; Mfr_part_number: GRM033R61C104KE14D; Mistral Part No: 120009030072-R; Package: 0201; Part_type: CAPACITORS\CERAMIC; Project: TI_MAXIE_CPB; RoHS: RoHS; Temperature: -55°C+85°C; Tolerance: 10%; Voltage: 16V; Wattage: NA; Weight: 0.33mg; Datasheet: Y:\MIS_DATABASE\DATASHEETS\CAPACITORS\GRM033R61C104KE14.PDF
FL23 = EMIFILTER_IND: IND FERRITE BEAD CHIP 120E 2A 0402; Chkd/date: NAVEED/241114; Crtd /date: USMAN/170613; Custom_Duty: 24%; Customs_HS_Code: 85369090; Distributor_name: DIGIKEY; Distributor_part_number: 490-9656-1-ND; Footprint Path: Y:\MIS_DATABASE\Library\ALTIUM_TOOL\PCB_FOOTPRINTS\Altium_Footprint_Lib.PcbLib; Height: 0.55MM; Library Path: Y:\MIS_DATABASE\Library\ALTIUM_TOOL\SCHEMATICS_PARTS\MS_FILTER_Library.schlib; Mfr_name: MURATA; Mfr_part_number: BLM15PX121SN1D; Mistral Part No: 130013060022-R; Package: 0402; Part_type: INDUCTOR; Project: GEN_3-8; RoHS: RoHS; Temperature: -55°C+125°C; Tolerance: 25%; Voltage: NA; Wattage: NA; Weight: 1mg; Datasheet: Y:\MIS_DATABASE\DATASHEETS\DISCRETES\INDUCTORS\BLM15-SN1-SER.PDF
R98 R135 = RESISTOR: RES 240E 1/10W 1% 0402; Chkd/date: MAZHAR/150611; Crtd /date: BAVISH/020611; Custom_Duty: 15%; Customs_HS_Code: 85332119; Distributor_name: DIGIKEY; Distributor_part_number: P240LCT-ND; Footprint Path: Y:\MIS_DATABASE\Library\ALTIUM_TOOL\PCB_FOOTPRINTS\Altium_Footprint_Lib.PcbLib; Height: 0.40MM; Library Path: Y:\MIS_DATABASE\Library\ALTIUM_TOOL\SCHEMATICS_PARTS\MS_DISCRETE_Library.schlib; Mfr_name: PANASONIC-ECG; Mfr_part_number: ERJ-2RKF2400X; Mistral Part No: 110011060017-R; Package: 0402; Part_type: RESISTORS\FIXED; Project: AM4515_EVM_LCD; RoHS: RoHS; Temperature: -55°C+155°C; Tolerance: 1%; Voltage: NA; Wattage: 1/10W; Weight: 0.8mg; Datasheet: Y:\MIS_DATABASE\DATASHEETS\RESISTORS\PAN-ERJSER_NOV17.PDF
R118 R394 = RESISTOR: RES 10K 1/20W 5% 0201; Chkd/date: MANIRAJA/050517; Crtd /date: MANIRAJA/050517; Custom_Duty: 15%; Customs_HS_Code: 85332119; Distributor_name: DIGIKEY; Distributor_part_number: 311-10KNCT-ND; Footprint Path: Y:\MIS_DATABASE\Library\ALTIUM_TOOL\PCB_FOOTPRINTS\Altium_Footprint_Lib.PcbLib; Height: 0.26MM; Library Path: Y:\MIS_DATABASE\Library\ALTIUM_TOOL\SCHEMATICS_PARTS\MS_DISCRETE_Library.schlib; Mfr_name: YAGEO AMERICA; Mfr_part_number: RC0201JR-0710KL; Mistral Part No: 110010070051-R; Package: 0201; Part_type: RESISTORS\FIXED; Project: GOLDEN-I LITE; RoHS: RoHS; Temperature: -55°C+125°C; Tolerance: 5%; Voltage: NA; Wattage: 1/20W; Weight: 0.17mg; Datasheet: Y:\MIS_DATABASE\DATASHEETS\RESISTORS\RCXXXXL-SER_MAR18.PDF
R119 = RESISTOR: RES 2.2K 1/20W 5% 0201; Chkd/date: VASANTHA/010117; Crtd /date: MAZHAR/010605; Custom_Duty: 15%; Customs_HS_Code: 85332119; Distributor_name: DIGIKEY; Distributor_part_number: P2.2KAGCT-ND; Footprint Path: Y:\MIS_DATABASE\Library\ALTIUM_TOOL\PCB_FOOTPRINTS\Altium_Footprint_Lib.PcbLib; Height: 0.26MM; Library Path: Y:\MIS_DATABASE\Library\ALTIUM_TOOL\SCHEMATICS_PARTS\MS_DISCRETE_Library.schlib; Mfr_name: PANASONIC-ECG; Mfr_part_number: ERJ-1GEJ222C; Mistral Part No: 110009030427-R; Package: 0201; Part_type: RESISTORS\FIXED; Project: G4SLIM; RoHS: RoHS; Temperature: -55°C+125°C; Tolerance: 5%; Voltage: NA; Wattage: 1/20W; Weight: 0.15mg; Datasheet: Y:\MIS_DATABASE\DATASHEETS\RESISTORS\PAN-ERJXGE-FEB06.PDF
R120 = RESISTOR: RES 10K 1/16W 5% 0402; Chkd/date: MANIRAJA/120219; Crtd /date: MANIRAJA/120219; Custom_Duty: 15%; Customs_HS_Code: 85332119; Distributor_name: DIGIKEY; Distributor_part_number: 541-10KJCT-ND; Footprint Path: Y:\MIS_DATABASE\Library\ALTIUM_TOOL\PCB_FOOTPRINTS\Altium_Footprint_Lib.PcbLib; Height: 0.40MM; Library Path: Y:\MIS_DATABASE\Library\ALTIUM_TOOL\SCHEMATICS_PARTS\MS_DISCRETE_Library.schlib; Mfr_name: VISHAY; Mfr_part_number: CRCW040210K0JNED; Mistral Part No: 110011060021-R; Package: 0402; Part_type: RESISTORS\FIXED; Project: NEXTNAV_ORBIT_MODULE; RoHS: RoHS; Temperature: -55°C+155°C; Tolerance: 5%; Voltage: NA; Wattage: 1/16W; Weight: 0.65mg; Datasheet: Y:\MIS_DATABASE\DATASHEETS\RESISTORS\CRCW0603.PDF
R121 = RESISTOR: RES 1K 1/10W 1% 0402; Chkd/date: VASANTHA/281216; Crtd /date: MAZHAR/150506; Custom_Duty: 15%; Customs_HS_Code: 85332119; Distributor_name: DIGIKEY; Distributor_part_number: P1.00KLCT-ND; Footprint Path: Y:\MIS_DATABASE\Library\ALTIUM_TOOL\PCB_FOOTPRINTS\Altium_Footprint_Lib.PcbLib; Height: 0.40MM; Library Path: Y:\MIS_DATABASE\Library\ALTIUM_TOOL\SCHEMATICS_PARTS\MS_DISCRETE_Library.schlib; Mfr_name: PANASONIC-ECG; Mfr_part_number: ERJ-2RKF1001X; Mistral Part No: 110009030411-R; Package: 0402; Part_type: RESISTORS\FIXED; Project: VOCERA; RoHS: RoHS; Temperature: -55°C+155°C; Tolerance: 1%; Voltage: NA; Wattage: 1/10W; Weight: 0.8mg; Datasheet: Y:\MIS_DATABASE\DATASHEETS\RESISTORS\PAN-ERJSER_NOV17.PDF
R122 = RESISTOR: RES 1K 1/10W 5% 0402; Chkd/date: VASANTHA/201216; Crtd /date: MAZHAR/230805; Custom_Duty: 15%; Customs_HS_Code: 85332119; Distributor_name: DIGIKEY; Distributor_part_number: P1.0KJCT-ND; Footprint Path: Y:\MIS_DATABASE\Library\ALTIUM_TOOL\PCB_FOOTPRINTS\Altium_Footprint_Lib.PcbLib; Height: 0.40MM; Library Path: Y:\MIS_DATABASE\Library\ALTIUM_TOOL\SCHEMATICS_PARTS\MS_DISCRETE_Library.schlib; Mfr_name: PANASONIC-ECG; Mfr_part_number: ERJ-2GEJ102X; Mistral Part No: 110009030400-R; Package: 0402; Part_type: RESISTORS\FIXED; Project: HSE; RoHS: RoHS; Temperature: -55°C+155°C; Tolerance: 5%; Voltage: NA; Wattage: 1/10W; Weight: 0.8mg; Datasheet: Y:\MIS_DATABASE\DATASHEETS\RESISTORS\PAN-ERJSER_NOV17.PDF
R395 R397 = RESISTOR: RES 39.2E 1/16W 1% 0402; Chkd/date: RAGESH/210411; Crtd /date: MAZHAR/210411; Custom_Duty: 15%; Customs_HS_Code: 85332119; Distributor_name: DIGIKEY; Distributor_part_number: RMCF0402FT39R2CT-ND; Footprint Path: Y:\MIS_DATABASE\Library\ALTIUM_TOOL\PCB_FOOTPRINTS\Altium_Footprint_Lib.PcbLib; Height: 0.40MM; Library Path: Y:\MIS_DATABASE\Library\ALTIUM_TOOL\SCHEMATICS_PARTS\MS_DISCRETE_Library.schlib; Mfr_name: STACKPOLE ELECTRONICS; Mfr_part_number: RMCF0402FT39R2; Mistral Part No: 110011040030-R; Package: 0402; Part_type: RESISTORS\FIXED; Project: AOD_POD-BASECARD; RoHS: RoHS; Temperature: -55°C+155°C; Tolerance: 1%; Voltage: NA; Wattage: 1/16W; Weight: 0.57mg; Datasheet: Y:\MIS_DATABASE\DATASHEETS\RESISTORS\RMCF-SER_JUL18.PDF
R407 R408 = RESISTOR: RES 1K 1/20W 1% 0201; Chkd/date: PRAVEEN/110822; Crtd /date: PRAVEEN/110822; Custom_Duty: 15%; Customs_HS_Code: 85332119; Distributor_name: DIGIKEY; Distributor_part_number: P122413CT-ND; Footprint Path: Y:\MIS_DATABASE\Library\ALTIUM_TOOL\PCB_FOOTPRINTS\Altium_Footprint_Lib.PcbLib; Height: 0.26MM; Library Path: Y:\MIS_DATABASE\Library\ALTIUM_TOOL\SCHEMATICS_PARTS\MS_DISCRETE_Library.schlib; Mfr_name: PANASONIC-ECG; Mfr_part_number: ERJ-1GNF1001C; Mistral Part No: 110022080039-R; Package: 0201; Part_type: RESISTORS\FIXED; Project: QCS6490 SOM_BRD; RoHS: RoHS; Temperature: -55°C+125°C; Tolerance: 1%; Voltage: NA; Wattage: 1/20W; Weight: 0.15mg; Datasheet: Y:\MIS_DATABASE\DATASHEETS\RESISTORS\PAN-ERJSER_NOV17.PDF
U29 = MT40A512M16LY_FBGA96: IC 16Gb DDR4 SDRAM FBGA96; Chkd/date: PRAVEEN/031122; Crtd /date: PRAVEEN/031122; Custom_Duty: 15%; Customs_HS_Code: 85423100; Distributor_name: DIGIKEY; Distributor_part_number: 557-MT40A1G16TB-062EIT:F-ND; Footprint Path: Y:\MIS_DATABASE\Library\ALTIUM_TOOL\PCB_FOOTPRINTS\Altium_Footprint_Lib.PcbLib; Height: 1.20MM; Library Path: Y:\MIS_DATABASE\Library\ALTIUM_TOOL\SCHEMATICS_PARTS\MS_MISCMEMORY_Library.schlib; Mfr_name: MICRON; Mfr_part_number: MT40A1G16TB-062E IT:F; Mistral Part No: 141022110006-R; Package: FBGA96; Part_type: ICS\DIGITAL\MEMORY; Project: AM64x_SK_BRD; RoHS: RoHS; Temperature: -40°C+95°C; Tolerance: NA; Voltage: NA; Wattage: NA; Weight: NA; Datasheet: Y:\MIS_DATABASE\DATASHEETS\ICS\MEMORY\MT40A-SER.PDF
U12 = AM62-EVM_BGA425: IC AM62 SoC MICROPROCESSOR BGA425; Chkd/date: ALVY/110621; Crtd /date: MANIRAJA/110621; Custom_Duty: 15%; Customs_HS_Code: 85423100; Distributor_name: NA; Distributor_part_number: NA; Footprint Path: Y:\MIS_DATABASE\Library\ALTIUM_TOOL\PCB_FOOTPRINTS\Altium_Footprint_Lib.PcbLib; Height: 0.65MM; Library Path: Y:\MIS_DATABASE\Library\ALTIUM_TOOL\SCHEMATICS_PARTS\MS_MICROPROCESSOR_Library.schlib; Mfr_name: TEXAS INSTRUMENTS; Mistral Part No: 141221060001; Package: BGA425; Part_type: ICS\DIGITAL\MICROPROCESSOR; Project: AM62_EVM_BRD; RoHS: NA; Temperature: NA; Tolerance: NA; Voltage: NA; Wattage: NA; Weight: NA; Datasheet: Y:\MIS_DATABASE\DATASHEETS\ICS\DIGITAL\MICROCONTROLLER\AM62-SoC_SVB.PDF

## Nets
DGND: C31.2 C34.2 C36.2 C37.1 C40.2 C42.2 C44.2 C55.2 C56.2 C74.2 C80.2 C81.2 C82.2 C83.2 C85.2 C99.2 C102.1 C116.2 C205.2 C214.2 C215.1 C218.2 C226.2 C233.2 C239.2 C240.2 C241.2 C244.2 C247.2 C249.1 C250.2 C251.2 C252.2 C253.2 C254.2 C255.2 C256.2 C257.2 C258.2 C259.2 C260.2 C261.2 C262.2 C264.2 C265.2 C266.2 C267.2 C268.2 C269.2 C271.2 C272.2 C273.2 C274.2 C276.2 C277.2 C278.2 C279.2 C280.2 C282.2 C286.2 C291.2 C292.2 C293.2 C294.2 C295.2 C302.2 C309.2 C310.2 C311.2 C313.2 C314.2 C328.1 C329.2 C332.2 C336.2 C339.2 C340.2 C343.2 C344.2 C346.2 C347.2 C349.2 C350.2 C351.2 C352.1 C354.2 C358.2 C359.2 C362.2 C363.1 C365.2 C493.2 C519.1 C525.2 R98.2 R108.2 R120.2 R122.1 R135.2 R394.2 R407.2 U8.B3(A0) U8.C1(GND) U12.A1(VSS) U12.A24(VSS) U12.A25(VSS) U12.AA11(VSS) U12.AB9(VSS) U12.AD1(VSS) U12.AD9(VSS) U12.AD12(VSS) U12.AD16(VSS) U12.AD25(VSS) U12.AE1(VSS) U12.AE8(VSS) U12.AE12(VSS) U12.AE16(VSS) U12.AE24(VSS) U12.AE25(VSS) U12.B25(VSS) U12.F13(VSS) U12.G13(VSS) U12.G19(VSS) U12.H13(VSS) U12.H16(VSS) U12.H18(VSS) U12.H20(VSS) U12.J7(VSS) U12.J13(VSS) U12.K7(VSS) U12.K13(VSS) U12.K15(VSS) U12.K19(VSS) U12.L20(VSS) U12.M7(VSS) U12.M8(VSS) U12.M10(VSS) U12.M12(VSS) U12.M13(VSS) U12.M17(VSS) U12.M18(VSS) U12.N15(VSS) U12.P7(VSS) U12.P10(VSS) U12.P13(VSS) U12.R13(VSS) U12.R15(VSS) U12.R18(VSS) U12.R20(VSS) U12.T8(VSS) U12.T13(VSS) U12.T14(VSS) U12.T16(VSS) U12.T17(VSS) U12.T18(VSS) U12.U8(VSS) U12.U19(VSS) U12.V9(VSS) U12.V10(VSS) U12.V11(VSS) U12.V13(VSS) U12.V16(VSS) U12.V18(VSS) U12.W7(VSS) U12.Y2(VSS) U16.C1(GND) U23.C1(GND) U25.C1(GND) U29.A2(VSSQ) U29.A8(VSSQ) U29.B2(VSS) U29.C9(VSSQ) U29.D2(VSSQ) U29.D8(VSSQ) U29.E1(VSS) U29.E3(VSSQ) U29.E8(VSSQ) U29.E9(VSS) U29.F1(VSSQ) U29.G8(VSS) U29.H1(VSSQ) U29.H9(VSSQ) U29.K1(VSS) U29.K9(VSS) U29.M9(VSS) U29.N1(VSS) U29.T1(VSS) U36.C1(GND) U36.C3(A1) U37.B3(A0) U37.C1(GND) U37.C3(A1) ; also on sheet 1 3 12 13 14 15 20 21 22 23 24 25 26 27 28 29 30 31 32 33 34 35 36 37 38 39 40 41 42 43 44 45
VCC_1V8_N: R79.2 ; also on sheet 15
VCC_1V8_P: R78.2 ; also on sheet 15
VCC_3V3_SYS: C74.1 C99.1 C116.1 C205.1 C332.1 C365.1 R386.2 U8.B1(VS) U16.B1(VS) U16.B3(A0) U16.C3(A1) U23.B1(VS) U23.B3(A0) U25.B1(VS) U25.C3(A1) U36.B1(VS) U36.B3(A0) U37.B1(VS) ; also on sheet 3 12 14 15 20 21 22 24 25 26 27 28 29 31 32 33 34 35 36 37 38 39 40 41 42 43 44 45
VCC_3V3_SYS_N: R37.2 ; also on sheet 15
VCC_3V3_SYS_P: R33.2 ; also on sheet 15
VCC_5V0: R375.1 ; also on sheet 12 13 35 38 43
VCC_CORE_N: R149.2 ; also on sheet 15
VCC_CORE_P: R155.2 ; also on sheet 15
VDD_1V2_N: R124.2 ; also on sheet 15
VDD_1V2_P: R125.2 ; also on sheet 15
VDD_2V5: FL23.1 ; also on sheet 15 25 26
VDD_CANUART: U12.F8(VDD_CANUART) ; also on sheet 14
VDD_CORE: C55.1 C56.1 C80.1 C244.1 C247.1 C250.1 C260.1 C261.1 C262.1 C267.1 C268.1 C273.1 C277.1 C280.1 C291.1 C293.1 C295.1 C309.1 C310.1 C311.1 R699.1 U12.H8(VDD_CORE) U12.J11(VDD_CORE) U12.J14(VDD_CORE) U12.K17(VDD_CORE) U12.L12(VDD_CORE) U12.L15(VDD_CORE) U12.M16(VDD_CORE) U12.N8(VDD_CORE) U12.N11(VDD_CORE) U12.N13(VDD_CORE) U12.P17(VDD_CORE) U12.R11(VDD_CORE) U12.R14(VDD_CORE) U12.U12(VDD_CORE) U12.V8(VDD_CORE) U12.V15(VDD_CORE) U12.V17(VDD_CORE) ; also on sheet 1 15
VDD_DDR4: C81.1 C82.1 C83.1 C85.1 C282.1 C292.1 C313.1 C314.1 C329.1 C336.1 C337.2 C339.1 C340.1 C343.1 C344.1 C346.1 C347.1 C349.1 C350.1 C354.1 C358.1 C359.1 C361.2 R118.2 R119.2 R121.2 R408.1 U12.K9(VDDS_DDR) U12.L8(VDDS_DDR) U12.M9(VDDS_DDR_C) U12.P9(VDDS_DDR) U12.R8(VDDS_DDR) U29.A1(VDDQ) U29.A9(VDDQ) U29.B3(VDD) U29.B9(VDD) U29.C1(VDDQ) U29.D1(VDD) U29.D9(VDDQ) U29.F2(VDDQ) U29.F8(VDDQ) U29.G1(VDDQ) U29.G7(VDD) U29.G9(VDDQ) U29.J1(VDD) U29.J2(VDDQ) U29.J8(VDDQ) U29.J9(VDD) U29.L1(VDD) U29.L9(VDD) U29.R1(VDD) U29.T9(VDD) ; also on sheet 15
VDD_LDO2_N: R145.2 ; also on sheet 15
VDD_LDO2_P: R147.2 ; also on sheet 15
VDDA1V8_N: R115.2 ; also on sheet 15
VDDA1V8_P: R109.2 ; also on sheet 15
VDDA_1V8: C493.1 U12.G7(VDDS_OSC0) U12.G16(VDDA_TEMP1) U12.T9(VDDA_TEMP0) ; also on sheet 1 15
VDDA_1V8_CSIRX: U12.W14(VDDA_1P8_CSIRX0) ; also on sheet 1
VDDA_1V8_MCU: U12.L11(VDDA_MCU) ; also on sheet 1
VDDA_1V8_OLDI: U12.W9(VDDA_1P8_OLDI0) U12.W10(VDDA_1P8_OLDI0) ; also on sheet 1
VDDA_1V8_USB: U12.Y11(VDDA_1P8_USB) ; also on sheet 1
VDDA_CORE_CSI: U12.W13(VDDA_CORE_CSIRX0) ; also on sheet 1
VDDA_CORE_USB: U12.W12(VDDA_CORE_USB) ; also on sheet 1
VDDA_PLL0: U12.U11(VDDA_PLL0) ; also on sheet 1
VDDA_PLL1: U12.U15(VDDA_PLL1) ; also on sheet 1
VDDA_PLL2: U12.L14(VDDA_PLL2) ; also on sheet 1
VDDA_SYS_MON: C519.2 R108.1 R375.2 U12.H10(VMON_VSYS)
VDDR_CORE: C214.1 C215.2 C240.1 C241.1 C264.1 C271.1 C274.1 C279.1 R699.2 U12.J12(VDDR_CORE) U12.K16(VDDR_CORE) U12.N12(VDDR_CORE) U12.N14(VDDR_CORE) U12.P16(VDDR_CORE) U12.R12(VDDR_CORE) U12.T10(VDDR_CORE) U12.U14(VDDR_CORE) ; also on sheet 15
CAN_IO_3V3: U12.H9(VDDSHV_CANUART) ; also on sheet 1 33 36
CAP_VDDS0: C269.1 U12.H15(CAP_VDDS0)
CAP_VDDS1: C257.1 U12.K18(CAP_VDDS1)
CAP_VDDS2: C256.1 U12.W17(CAP_VDDS2)
CAP_VDDS3: C251.1 U12.P19(CAP_VDDS3)
CAP_VDDS4: C302.1 U12.U7(CAP_VDDS4)
CAP_VDDS5: C258.1 U12.H17(CAP_VDDS5)
CAP_VDDS6: C239.1 U12.J19(CAP_VDDS6)
CAP_VDDS_CANUART: C294.1 U12.G9(CAP_VDDS_CANUART)
CAP_VDDS_MCU: C276.1 U12.H11(CAP_VDDS_MCU)
DDR_A0: U12.J1(DDR0_A0) U29.P3(A0)
DDR_A1: U12.J2(DDR0_A1) U29.P7(A1)
DDR_A2: U12.K3(DDR0_A2) U29.R3(A2)
DDR_A3: U12.L5(DDR0_A3) U29.N7(A3)
DDR_A4: U12.K4(DDR0_A4) U29.N3(A4)
DDR_A5: U12.K1(DDR0_A5) U29.P8(A5)
DDR_A6: U12.R2(DDR0_A6) U29.P2(A6)
DDR_A7: U12.P2(DDR0_A7) U29.R8(A7)
DDR_A8: U12.P1(DDR0_A8) U29.R2(A8)
DDR_A9: U12.P4(DDR0_A9) U29.R7(A9)
DDR_A10: U12.R5(DDR0_A10) U29.M3(A10/AP)
DDR_A11: U12.P5(DDR0_A11) U29.T2(A11)
DDR_A12: U12.R6(DDR0_A12) U29.M7(A12/BC_N)
DDR_A13: U12.R1(DDR0_A13) U29.T8(A13)
DDR_A14_WEn: U12.N3(DDR0_WE_N) U29.L2(WE_N/A14)
DDR_A15_CAS: U12.M4(DDR0_CAS_N) U29.M8(CAS_N/A15)
DDR_A16_RAS: U12.M5(DDR0_RAS_N) U29.L8(RAS_N/A16)
DDR_ACTn: U12.N6(DDR0_ACT_N) U29.L3(ACT_N)
DDR_ALERTn: R118.1 U12.R3(DDR0_ALERT_N) U29.P9(ALERT_N)
DDR_BA0: U12.M1(DDR0_BA0) U29.N2(BA0)
DDR_BA1: U12.N1(DDR0_BA1) U29.N8(BA1)
DDR_BG0: U12.T4(DDR0_BG0) U29.M2(BG0)
DDR_CKE: R394.1 U12.H2(DDR0_CKE0) U29.K2(CKE)
DDR_CLKN: R395.1 U12.L2(DDR0_CK0_N) U29.K8(CK_C)
DDR_CLKP: R397.1 U12.L1(DDR0_CK0) U29.K7(CK_T)
DDR_CSn: U12.L6(DDR0_CS0_N) U29.L7(CS_N)
DDR_DQ0: U12.F4(DDR0_DQ0) U29.G2(DQ0)
DDR_DQ1: U12.H6(DDR0_DQ3) U29.F7(DQ1)
DDR_DQ2: U12.E3(DDR0_DQ4) U29.H3(DQ2)
DDR_DQ3: U12.F3(DDR0_DQ2) U29.H7(DQ3)
DDR_DQ4: U12.F1(DDR0_DQ7) U29.H2(DQ4)
DDR_DQ5: U12.G5(DDR0_DQ1) U29.H8(DQ5)
DDR_DQ6: U12.G2(DDR0_DQ5) U29.J3(DQ6)
DDR_DQ7: U12.F2(DDR0_DQ6) U29.J7(DQ7)
DDR_DQ8: U12.U1(DDR0_DQ8) U29.A3(DQ8)
DDR_DQ9: U12.U3(DDR0_DQ9) U29.B8(DQ9)
DDR_DQ10: U12.U2(DDR0_DQ10) U29.C3(DQ10)
DDR_DQ11: U12.V5(DDR0_DQ11) U29.C7(DQ11)
DDR_DQ12: U12.W2(DDR0_DQ12) U29.C2(DQ12)
DDR_DQ13: U12.V6(DDR0_DQ13) U29.C8(DQ13)
DDR_DQ14: U12.Y1(DDR0_DQ14) U29.D3(DQ14)
DDR_DQ15: U12.W1(DDR0_DQ15) U29.D7(DQ15)
DDR_LDM: U12.H5(DDR0_DM0) U29.E7(NF/LDM_N/LDBI_N)
DDR_LDQS_N: U12.E2(DDR0_DQS0_N) U29.F3(LDQS_C)
DDR_LDQS_P: U12.E1(DDR0_DQS0) U29.G3(LDQS_T)
DDR_ODT: U12.H1(DDR0_ODT0) U29.K3(ODT)
DDR_PARITY: U12.T1(DDR0_PAR) U29.T3(PAR)
DDR_RESET#: R119.1 R120.1 U12.G1(DDR0_RESET0_N) U29.P1(RESET_N)
DDR_TEN: R121.1 R122.2 U29.N9(TEN)
DDR_UDM: U12.W5(DDR0_DM1) U29.E2(NF/UDM_N/UDBI_N)
DDR_UDQS_N: U12.V2(DDR0_DQS1_N) U29.A7(UDQS_C)
DDR_UDQS_P: U12.V1(DDR0_DQS1) U29.B7(UDQS_T)
DDR_VPP: C328.2 C351.1 C352.2 FL23.2 U29.B1(VPP) U29.R9(VPP)
DDR_VREFCA: C102.2 C361.1 C362.1 C363.2 R407.1 R408.2 TP43.1(TP) U29.M1(VREFCA)
INA_ALERT: R93.2 R110.2 R113.2 R146.2 R154.2 R290.2 R386.1 TP37.1(TP)
RSVD8: U12.E7(RSVD8)
SOC_DVDD1V8: C36.1 C37.2 C40.1 C233.1 C252.1 C253.1 U12.G10(VMON_1P8_SOC) U12.J18(VDDSHV6) U12.L18(VDDSHV1) U12.M19(VDDSHV1) U12.T7(VDDSHV4) ; also on sheet 15
SoC_DVDD3V3: C31.1 C34.1 C42.1 C44.1 C218.1 C226.1 C249.2 C254.1 C255.1 C259.1 C265.1 C266.1 C272.1 C278.1 C286.1 U12.F11(VDDSHV_MCU) U12.F15(VDDSHV0) U12.G12(VDDSHV_MCU) U12.G14(VDDSHV0) U12.K10(VMON_3P3_SOC) U12.N18(VDDSHV3) U12.P18(VDDSHV3) U12.T19(VDDSHV3) U12.U18(VDDSHV3) U12.W16(VDDSHV2) U12.W19(VDDSHV2) U12.Y13(VDDA_3P3_USB) ; also on sheet 15
SOC_I2C1_SCL: U8.A1(SCL) U8.C3(A1) U16.A1(SCL) U23.A1(SCL) U23.C3(A1) U25.A1(SCL) U25.B3(A0) U36.A1(SCL) U37.A1(SCL) ; also on sheet 3 24 28 41 42 43 44
SOC_I2C1_SDA: U8.A2(SDA) U16.A2(SDA) U23.A2(SDA) U25.A2(SDA) U36.A2(SDA) U37.A2(SDA) ; also on sheet 3 24 28 41 42 43 44
SoC_VDDSHV5_SDIO: U12.G17(VDDSHV5) ; also on sheet 1
VPP_1V8: C525.1 U12.J8(VPP) ; also on sheet 14
N15835426: R135.1 U29.F9(ZQ)
N15835430: TP35.1(TP) U29.T7(NF/NC)
N16839912: C64.1 R78.1 U16.D3(IN+)
N16839940: C96.1 R109.1 U23.D3(IN+)
N16839975: C103.1 R125.1 U25.D3(IN+)
N16887346: R98.1 U12.M2(DDR0_CAL0)
N17010152: C337.1 R395.2 R397.2
N17153511: C18.2 R37.1 U8.D1(BUS) U8.D2(IN-)
N17153515: C18.1 R33.1 U8.D3(IN+)
N17153681: C121.1 R155.1 U37.D3(IN+)
N17153685: C121.2 R149.1 U37.D1(BUS) U37.D2(IN-)
N17153701: C119.2 R145.1 U36.D1(BUS) U36.D2(IN-)
N17153703: C119.1 R147.1 U36.D3(IN+)
N17153749: C64.2 R79.1 U16.D1(BUS) U16.D2(IN-)
N17153787: C96.2 R115.1 U23.D1(BUS) U23.D2(IN-)
N17153799: C103.2 R124.1 U25.D1(BUS) U25.D2(IN-)
N17153878: R146.1 U36.A3(ALERT)
N17153949: R93.1 U16.A3(ALERT)
N17153951: R110.1 U23.A3(ALERT)
N17154063: R113.1 U25.A3(ALERT)
N18516151: R154.1 U37.A3(ALERT)
N18520654: R290.1 U8.A3(ALERT)

Not connected (* = marked no-connect by the designer): U8 B2(NC1)* C2(NC2)*; U12 J3(DDR0_ODT1)* J4(DDR0_CKE1)* K2(DDR0_CS1_N)* N2(DDR0_BG1)* T2(RSVD4)* U4(RSVD5)*; U16 B2(NC1)* C2(NC2)*; U23 B2(NC1)* C2(NC2)*; U25 B2(NC1)* C2(NC2)*; U36 B2(NC1)* C2(NC2)*; U37 B2(NC1)* C2(NC2)*

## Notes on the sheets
sheet 16
- CURRENT MEASUREMENT DEVICES
- D-Note: Note the supply rail name change across the shunt when optimizing
  the design (Deleting the current sense resistor).
- D-Note: Provision for 4-wire resistor and
  current measurement devices have been
  provided for testing on the EVM board.
  Implementing current measurement circuit
  on the custom board is use case and board
  requirements dependent.
- VDD_CORE
- SoC_DVDD1V8
- CAD Note:
  Follow Kelvin current
  sense connection
  when 2 terminal (wire)
  resistor is used
- I2C ADDRESS: 0x40
- I2C ADDRESS: 0x45
- VDDR_CORE
- VDDA_1V8
- I2C ADDRESS: 0x4D
- I2C ADDRESS: 0x41
- SoC_DVDD3V3
- VDD_DDR4
- I2C ADDRESS: 0x4C
- I2C ADDRESS: 0x47
- D-Note:
  0R resistor option to connect VDDR_CORE  to VDD_CORE supply rail.
  The recommendation is to connect VDD_CORE and VDDR_CORE to the same
  supply source when VDD_CORE is configured for 0.85V.
- INA I2C SLAVE ADDRESS
- SLAVE
  ADDRESS
  (IN HEX)
- POWER SOURCE
- SUPPLY NET
- VCC_CORE
- VDD_CORE
- 40
- VCC_3V3_SYS
- SoC_DVDD3V3
- 4C
- VCC_1V8
- SoC_DVDD1V8
- 45
- CORE SUPPLY
- ARRAY CORE SUPPLY
- Assembly
- VDDA1V8
- VDDA_1V8
- 4D
- 0.75 VDD_CORE
- 0.85 VDDR_CORE
- DNI R699 and Mount R123
- VCC1V2_DDR
- VDD_DDR4
- 47
- 0.85 VDD_CORE
- 0.85 VDDR_CORE
- DNI R123 and Mount R699
sheet 17
- SOC POWER SUPPLIES AND SUPPLY RAILS
- D-Note:
  Recommend implementing the voltage monitoring functionality using VMON_VSYS for early
  detection of supply failure. It is meant to be a power-fail indicator for the main input
  (higher) voltage rail that enters the custom board. For example, 5, 12, or 24 volts. The error
  associated with this monitor would require you to set the threshold of the monitored voltage
  significantly lower than the nominal voltage (ROC) to avoid a false trigger. Refer to System
  Power Supply Monitor Design Guidelines section of the data sheet.
- D-Note:
  Changing the core voltage
  (Dynamically) is not allowed
  after the SOC has been
  released from reset. In case
  the core supply is turned off,
  the recommendation is to
  turn off all power rails and
  ramp them down as per the
  power-down sequence and wait
  until all supply rails decay
  below 300mV before turning
  on power again.
- V
- D-Note:
  VDD_CORE and VDDR_CORE are recommended to be
  connected to the same supply source, so they
  ramp together when VDD_CORE is operating
  at 0.85 V.
- D-Note:
  Refer to the Pin Connectivity Requirements to
  connect the CSI0 supplies (analog and core),
  when CSI0 interface is not used. Ferrite and
  Bulk Caps are optional, when CSI0 is not used
  and boundary scan functionality is required.
- R-Note:
  Connecting a 1.8V supply source directly
  to VPP pin continuously is not
  recommended or allowed.
- D-Note:
  RESERVED PINS
  Leave them unconnected
- C
- D-Note:
  Refer to the pin connectivity requirements section  of the SoC data sheet for connecting the USB IO,
  analog and core supplies when USB interface is not used. It is allowed to have the supplies connected and
  all the USB pins left unconnected, provided the USB driver is not initialized at any time and the
  USB calibration procedure does not happen. The recommendation is to connect (Grounding) the USB supplies
  as per the pin connectivity requirements when not used, to optimize power when low power is a critical
  requirement.
- D-Note:
  A trace connected to SoC is effectively an antenna that will pick up noise.
  A potential will be generated on the signal when noise couples into
  the antenna. This potential will be largest on the highest impedance
  end of the signal. By placing a pull-up (pullup) or pull-down (pulldown)
  near the SoC pin, we force the highest potential to the open-circuit
  end of the signal rather than the SoC end of the signal.
- SOC VSS
- V.
- D-Note:
  Select capacitors with ESR < 1 ohm. Ensure the PCB loop
  inductance is < 2.5 nH. Select 0201 package or the smallest
  possible package.
sheet 18
- SOC POWER SUPPLIES - DECAPS 1
- CAD Note:
  Place 0.1 uF caps near to the SoC pins.
- CAD Note:
  Place 0.1 uF caps near to the SoC pins.
- CAD Note:
  Place 0.1 uF caps near to the SoC pins.
- CAD Note:
  Place 0.1 uF caps near to the SoC pins.
- CAD Note:
  Place 0.1 uF caps near to the SoC pins.
sheet 19
- SOC DDR4 INTERFACE
- D-Note:
  DDR DQ lines swapped
  within data byte.
- R-Note:
  Verify the need to connect DDR0_BG1
  on the custom board for memory expansion.
- D-Note:
  RESERVED PINS
  Leave them unconnected
- R-Note:
  Verify the need to connect the
  NC pins on the custom board
  for memory expansion.
- R-Note:
  Pull-down is populated.
- V
- DDR4 DEVICE
- D-Note:
  Refer TMDS64EVM for implementing VTT terminations for
  DDR4, address and control signals, when a single DDR
  device is used.
- R-Note:
  Pull-down is populated.
- R-Note:
  Pull-down is DNI.
